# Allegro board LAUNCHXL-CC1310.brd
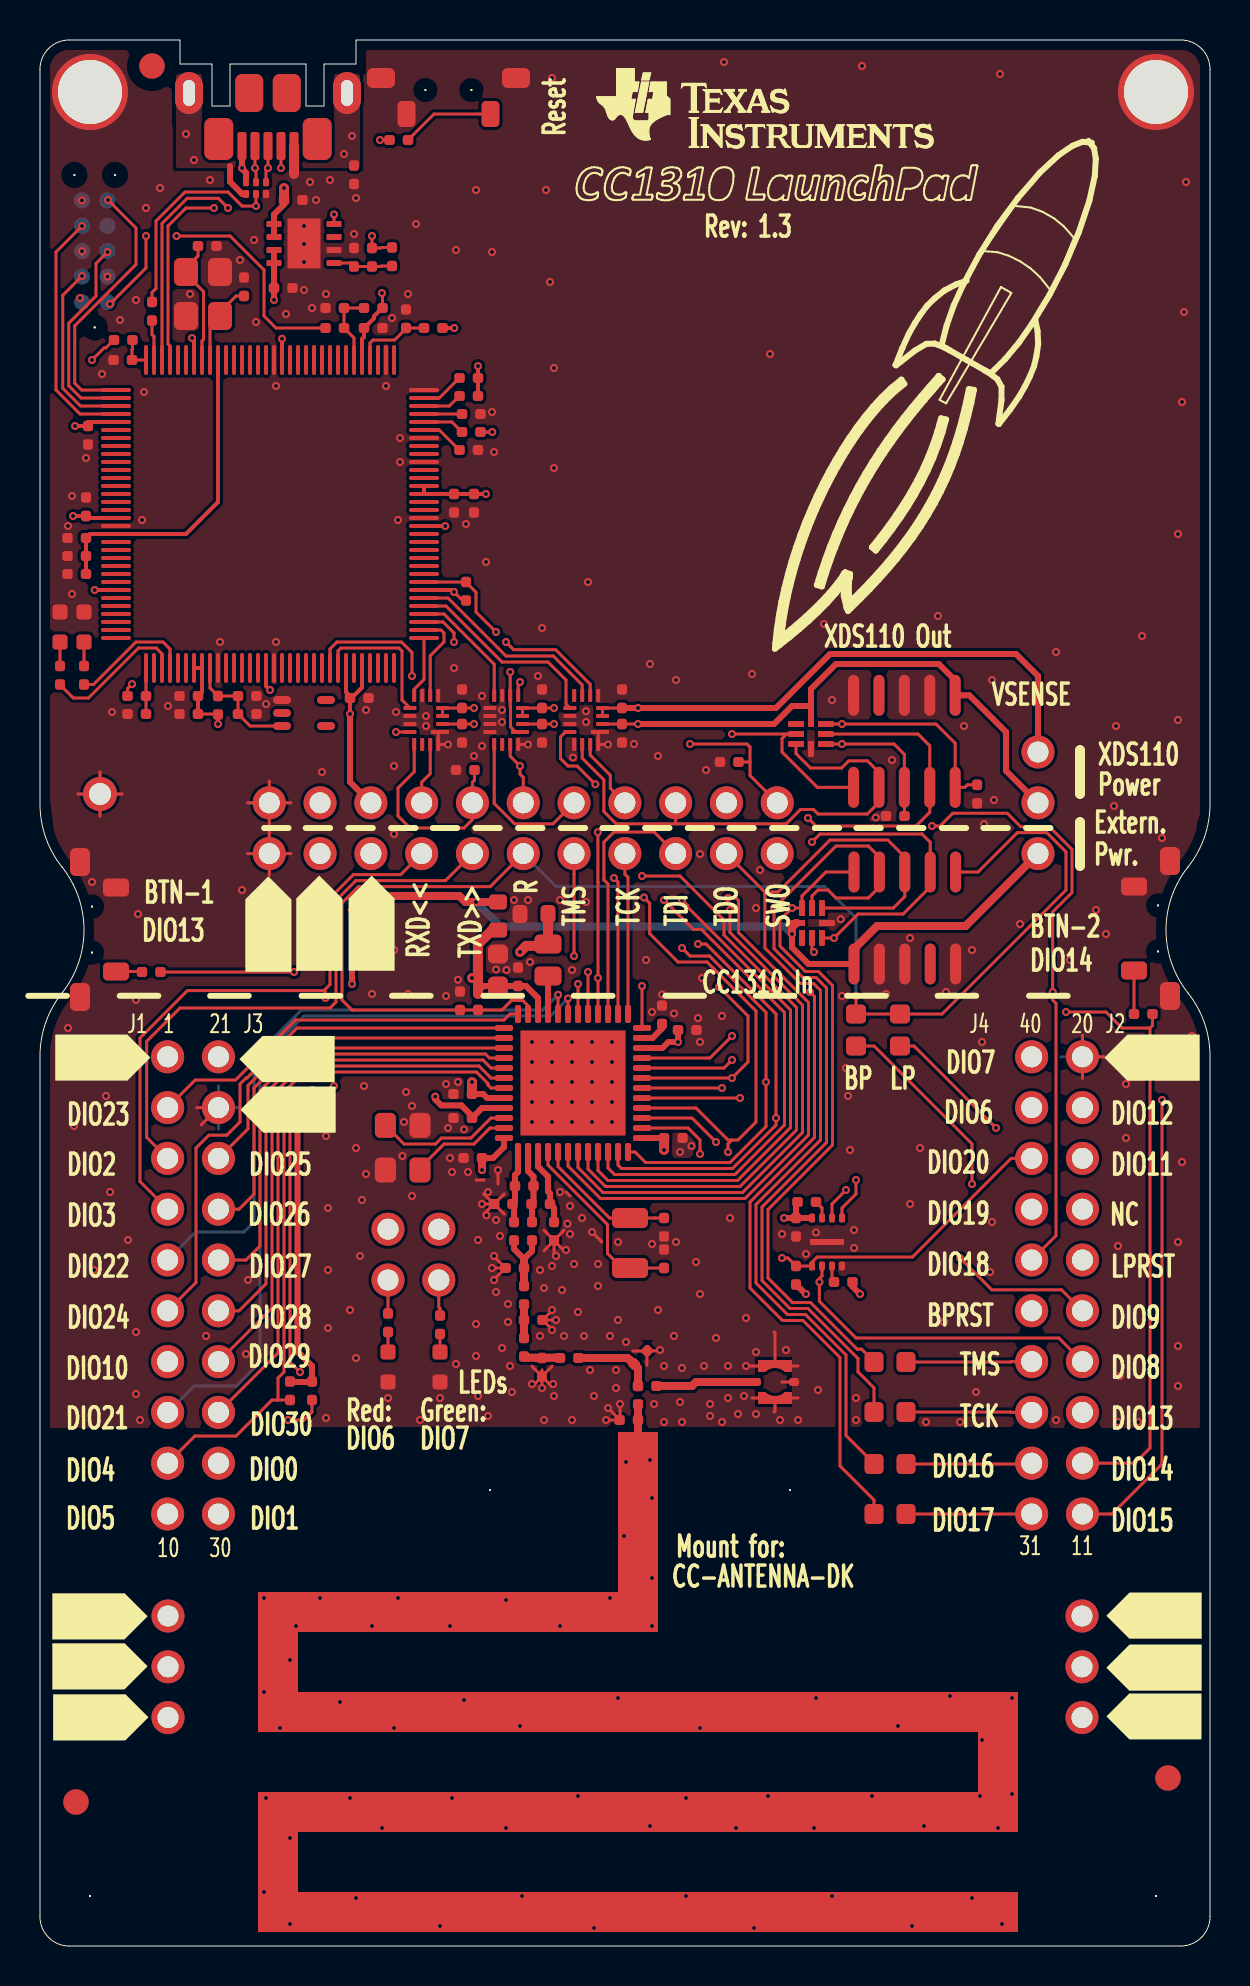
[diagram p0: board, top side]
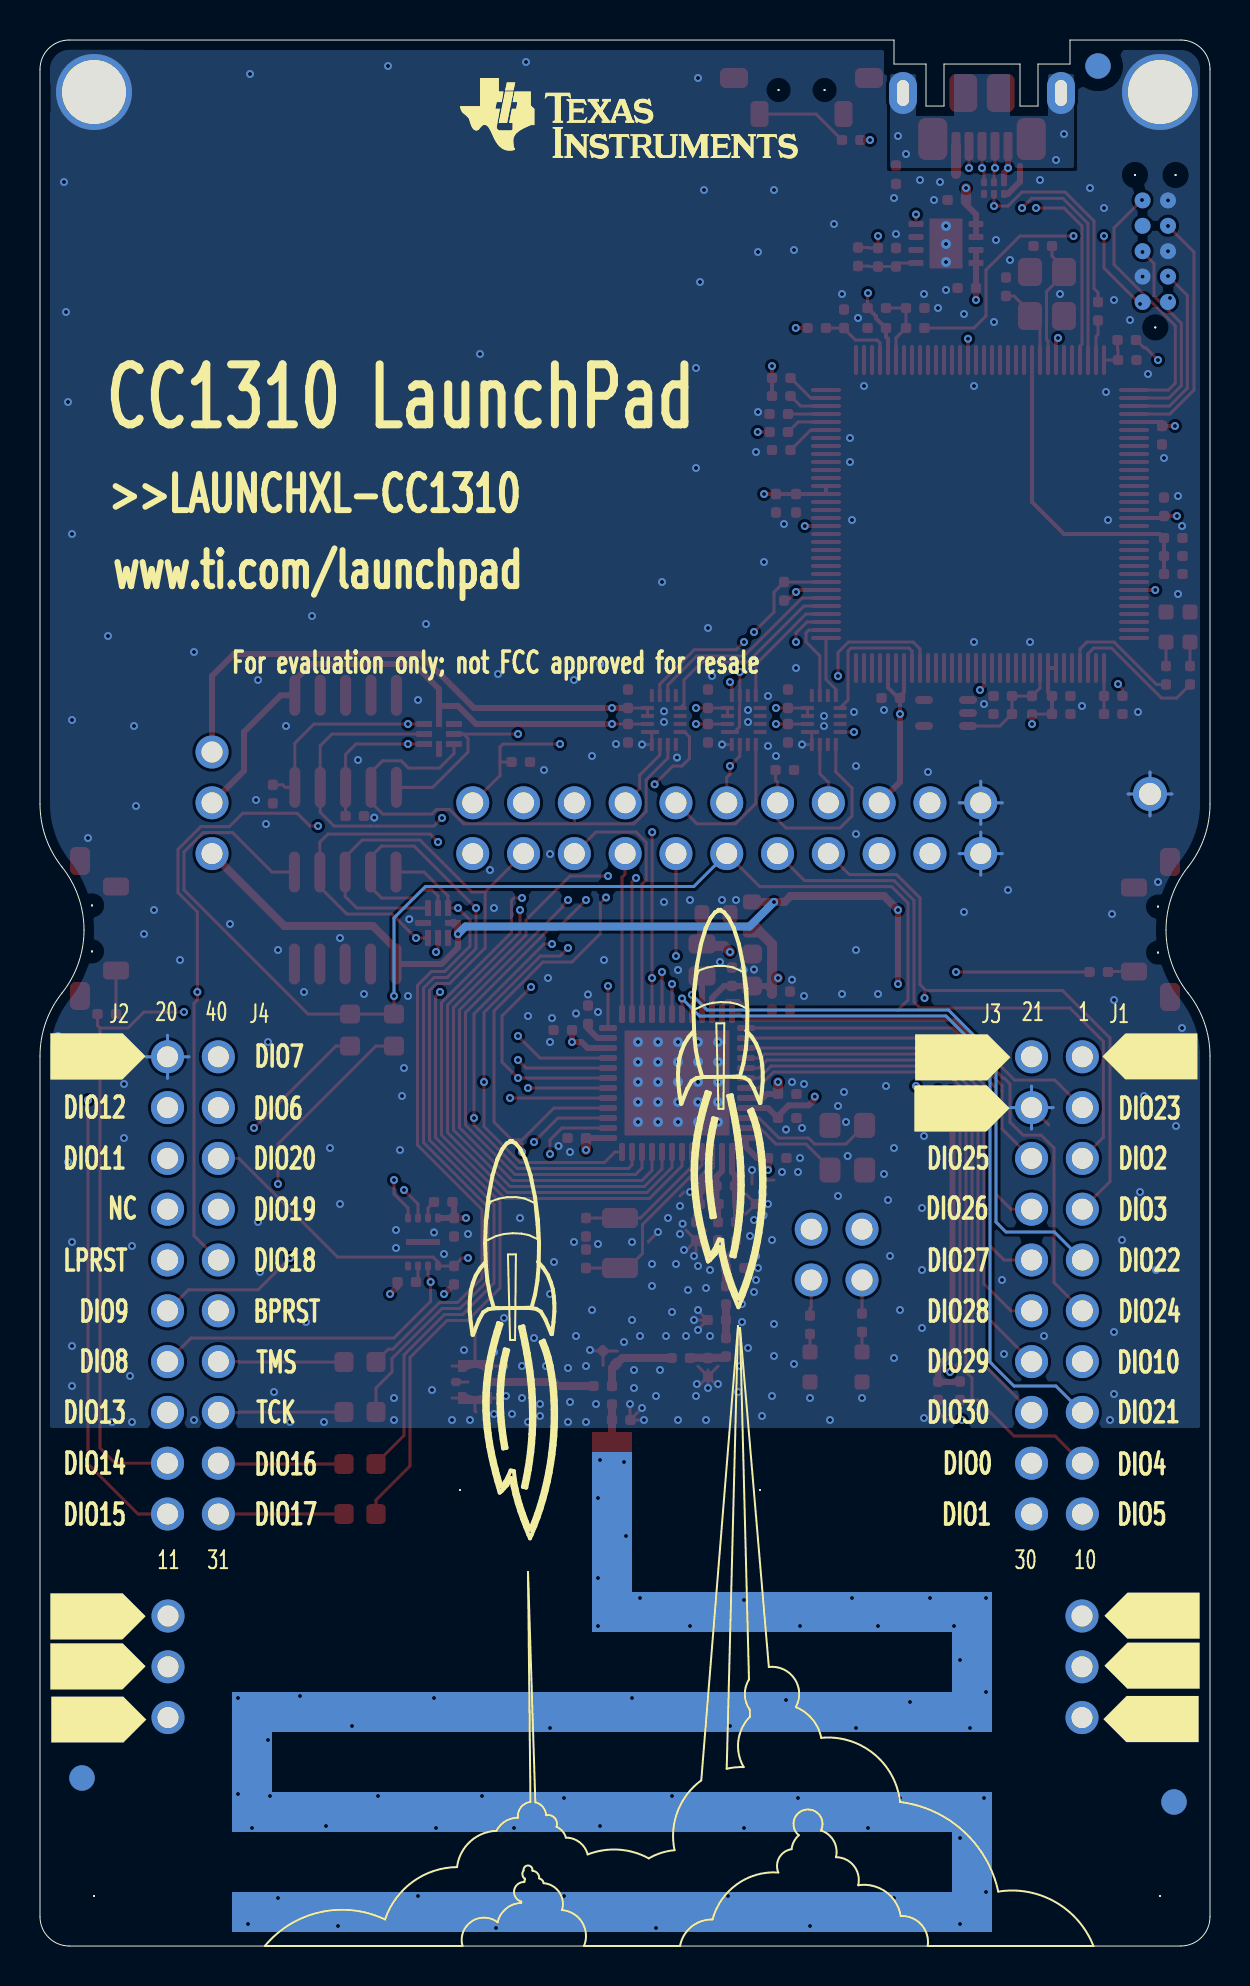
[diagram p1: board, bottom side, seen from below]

Outline 58.5 x 95.3 mm; copper layers: TOP, L2, L3, BOTTOM. Coordinates in mm from the lower left corner of the outline.
Outline path: 0,93.84 0,57.1 arc(0.28,55.43) 1.1,53.95 arc(1.92,52.47) 2.2,50.8 arc(1.92,49.13) 1.1,47.65 arc(0.28,46.17) 0,44.5 0,1.46 arc(0.43,0.43) 1.46,0 57.04,0 arc(58.07,0.43) 58.5,1.46 58.5,44.5 arc(58.22,46.17) 57.4,47.65 arc(56.58,49.13) 56.3,50.8 arc(56.58,52.47) 57.4,53.95 arc(58.22,55.43) 58.5,57.1 58.5,93.84 arc(58.07,94.87) 57.04,95.3 15.8,95.3 15.8,94.1 14.2,94.1 14.2,92 13.3,92 13.3,94.1 9.5,94.1 9.5,92 8.6,92 8.6,94.1 7,94.1 7,95.3 1.46,95.3 arc(0.43,94.87) 0,93.84

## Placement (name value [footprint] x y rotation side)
A1  868MHz/2440MHz  [ANTENNA_DN024N]  29.9 25.2 180 top
C3  100nF  [CAPC1005X60B2N]  31.2 40.4 0 top
C4  100nF  [CAPC1005X60B2N]  31.9 45.8 0 top
C5  100nF  [CAPC1005X60B2N]  21.6 42.6 180 top
C6  22uF  [CAPC1608X100A2N]  22.9 48 90 top
C7  100nF  [CAPC1005X60B2N]  23.9 48 90 top
C8  22uF  [CAPC1608X100A2L]  25.4 51.6 180 top
C9  100nF  [CAPC1005X60B2N]  22.1 39.4 180 top
C11  3.6pF  [CAPC1005X60B2N]  22.7 37.1 0 top
C12  2.7pF  [CAPC1005X60B2N]  24.2 33.9 180 top
C13  6.2pF  [CAPC1005X60B2N]  24.2 31.3 0 top
C14  3pF  [CAPC1005X60B2N]  25.1 29.4 270 top
C15  100pF  [CAPC1005X60B2N]  26 29.4 0 top
C16  100nF  [CAPC1005X60B2N]  21.6 41.4 180 top
C17  12pF  [CAPC1005X60B2N]  31.2 33.9 90 top
C18  12pF  [CAPC1005X60B2N]  31.2 36.4 270 top
C19  1uF  [CAPC1005X60B2N]  31.1 46.1 90 top
C20  100nF  [CAPC1005X60B2N]  21 46.8 90 top
C21  100pF  [CAPC1005X60B2N]  25.7 36.2 270 top
C22  3.6pF  [CAPC1005X60B2N]  24.6 36.2 270 top
C24  DNM  [CAPC1005X60B2N]  29.7 29.1 45 top
C30  100nF  [CAPC1005X60B2N]  37.8 36.4 270 top
C32  100nF  [CAPC1005X60B2N]  9.9 62.5 0 top
C33  12pF  [CAPC1005X60B2N]  10.2 82.5 90 top
C34  12pF  [CAPC1005X60B2N]  7.9 85 0 top
C35  10nF  [CAPC1005X60B2N]  15.5 62.4 0 top
C36  10nF  [CAPC1005X60B2N]  2.3 71.5 90 top
C37  10nF  [CAPC1005X60B2N]  2.4 76 270 top
C38  100nF  [CAPC1005X60B2N]  16.2 80.9 0 top
C39  100nF  [CAPC1005X60B2N]  20.7 72.6 270 top
C40  1uF  [CAPC1005X60B2N]  21.7 72.6 270 top
C41  10nF  [CAPC1005X60B2N]  7.9 62.5 180 top
C42  1uF  [CAPC1005X60B2N]  7.9 61.6 180 top
C43  100nF  [CAPC1005X60B2N]  2.3 70.4 180 top
C44  1uF  [CAPC1005X60B2N]  2.3 69.5 180 top
C45  2.2uF  [CAPC1005X60B2N]  2.3 68.6 180 top
C46  100nF  [CAPC1005X60B2N]  18.3 80.9 90 top
C47  15pF  [CAPC1005X60B2N]  16.6 84.9 270 top
C48  2.2uF  [CAPC1005X60B2N]  12.2 87.3 0 top
C49  2.2uF  [CAPC1005X60B2N]  11.7 82.9 0 top
C50  10nF  [CAPC1005X60B2N]  9.9 61.6 0 top
C52  100nF  [CAPC1005X60B2N]  21.1 61.9 90 top
C53  100nF  [CAPC1005X60B2N]  21.1 61.1 270 top
C54  100nF  [CAPC1005X60B2N]  25.1 61.9 90 top
C55  100nF  [CAPC1005X60B2N]  25.1 61.1 270 top
C56  100nF  [CAPC1005X60B2N]  29.1 61.9 90 top
C57  100nF  [CAPC1005X60B2N]  29.1 61.1 270 top
C58  DNM_0402  [CAPC1005X60B2N]  29.9 26.3 180 top
C59  100nF  [CAPC1005X60B2N]  4.6 79.3 180 top
CR1  LPL296-J2L2-25  [LEDC1707X65L]  20 28.2 90 top
CR2  LS L296-P2Q2-1  [LEDC1708X67L]  17.4 28.2 90 top
CR4  LS L296-P2Q2-1  [LEDC1708X67L]  1 66.7 270 top
CR5  LPL296-J2L2-25  [LEDC1707X65L]  2.2 66.7 270 top
CR6  TPD4E004DRY  [SON50P100X145X60-6N]  10.3 87.6 0 top
CR7  TPD6E004RSER  [QFN50P150X150X60-8N]  37.8 61.1 270 top
CR8  TPD6E004RSER  [QFN50P150X150X60-8N]  38.1 50.4 0 top
FIDU1  FIDU_1.27mm  [FID127X142]  5.6 94 0 top
FIDU2  FIDU_1.27mm  [FID127X142]  1.8 7.2 0 top
FIDU3  FIDU_1.27mm  [FID127X142]  56.4 8.4 0 top
FIDU4  FIDU_1.27mm  [FID127X142]  5.6 94 180 bottom
FIDU5  FIDU_1.27mm  [FID127X142]  1.8 7.2 180 bottom
FIDU6  FIDU_1.27mm  [FID127X142]  56.4 8.4 180 bottom
FL1  BLM18HE152SN1  [FIL_BLM18HE152SN1DL]  22.9 50.8 90 top
J1  SSQ-110-23-L-D  [SAMTEC_SSQ11023LD_A2B]  6.38 44.46 0 bottom
J2  SSQ-110-23-L-D  [SAMTEC_SSQ11023LD_A2B]  49.58 44.46 0 bottom
J6  105164-0001  [MOLEX_1051640001_A2N]  10.1 90 0 top
L1  6.8uH  [INDC2012X150L]  25.4 48.5 90 top
L12  7.5nH  [INDC1005X60B2N]  23.7 36.2 270 top
L13  6.8nH  [INDC1005X60B2N]  24.2 33 270 top
L14  6.8nH  [INDC1005X60B2N]  24.2 30.4 270 top
L22  27nH  [INDC1005X60B2N]  23.75 38 0 top
L23  7.5nH  [INDC1005X60B2N]  25.5 37.1 180 top
MH1  HOLE_3.2mm_NPL  [MTG320]  2.5 2.5 0 top
MH2  HOLE_3.2mm_NPL  [MTG320]  55.8 2.5 0 top
MH3  HOLE_3.2mm_PTH  [MTG320_380]  2.5 92.7 0 top
MH4  HOLE_3.2mm_PTH  [MTG320_380]  55.8 92.7 0 top
MH5  HOLE_1.1mm_PTH  [MTG110_170]  3 57.6 0 top
NOREF  -  []  0 79.15 0 top
NOREF#2  -  []  8.3 41.8 0 top
NOREF#3  -  []  51.5 42 0 top
NOREF#4  -  []  51.6 11.5 0 top
NOREF#5  #VALUE  [unnamed#2]  22.5 22.8 0 top
NOREF#6  -  []  17.8 48.7 90 top
NOREF#7  -  []  16.5 46.3 90 top
NOREF#8  -  []  -1.7 11.6 0 top
NOREF#9  -  []  13.8 46.4 90 top
NOREF#10  -  []  40.01 0 90 top
NOREF#11  -  []  -1.7 14.1 0 top
NOREF#12  -  []  51.6 14.1 0 top
NOREF#13  -  []  -1.8 8.9 0 top
NOREF#14  -  []  53.1 10.1 0 top
NOREF#15  -  []  0.7 43.2 0 top
NOREF#16  -  []  8.3 39.4 0 top
NOREF#17  -  []  58 10.1 180 bottom
NOREF#18  -  []  7 8.8 180 bottom
NOREF#19  -  []  60.3 14.1 180 bottom
NOREF#20  -  []  60.3 11.6 180 bottom
NOREF#21  -  []  17.1 39.5 180 bottom
NOREF#22  -  []  17.2 41.9 180 bottom
NOREF#23  -  []  5.6 43.1 180 bottom
NOREF#24  -  []  60.3 42.1 180 bottom
NOREF#25  -  []  7 11.6 180 bottom
NOREF#26  -  []  51.53 65.52 180 bottom
NOREF#27  -  []  7 14.1 180 bottom
P1  BB02-HC031-KB1-603000  [GRADCONN_BB02HC031KB1603000_A2B]  52.1 11.42 90 top
P2  BB02-HC031-KB1-603000  [GRADCONN_BB02HC031KB1603000_A2B]  6.4 11.42 90 top
P4  BB02-HJ221-KB1-603000  [GRADCONN_BB02HJ221KB160300_A2B]  36.86 57.16 180 top
P5  FTSH-105-01-F-DV-K  [SAMTEC_FTSH-105-01-F-DV-K-10L]  40.7 49.1 0 top
P6  BB02-HJ041-KB1-603000  [GRADCONN_BB02HJ041KB1603000_A2B]  17.4 33.3 0 top
P7  FTSH-105-01-F-DV-K  [SAMTEC_FTSH-105-01-F-DV-K-10L]  45.76 62.53 180 top
P8  TC2050-IDC-NL  [TAGCONNECT_TC2050IDCNLN]  2.1 82.2 90 bottom
P10  BB02-HC031-KB1-603000  [GRADCONN_BB02HC031KB1603000_A2B]  49.9 59.7 270 top
P11  MM5829-2700  [MURATA_MM58292700RJ4_A2N]  35.8 28.2 0 top
R1  100k  [RESC1005X40B2N]  21.9 46.8 90 top
R2  3.3k  [RESC1005X40B2N]  12.5 27.3 90 top
R3  3.3k  [RESC1005X40B2N]  13.6 27.3 90 top
R11  2.2k  [RESC1005X40B2N]  37.8 34 270 top
R12  1.8pF  [CAPC1005X60B2N]  29.9 28 270 top
R13  0  [RESC1005X40B2N]  29.9 28 0 top
R14  220  [RESC1005X40B2N]  17.4 30.7 90 top
R15  180  [RESC1005X40B2N]  20 30.6 90 top
R17  10k  [RESC1005X40B2N]  16.2 81.9 0 top
R18  4.7k  [RESC1005X40B2N]  8.9 62.5 270 top
R19  DNM  [RESC1005X40B2N]  5.6 82.2 270 top
R20  100  [RESC1005X40B2N]  15.2 80.9 180 top
R21  DNM  [RESC1005X40B2N]  15.2 81.9 180 top
R22  330k  [RESC1005X40B2N]  5.3 62.5 180 top
R23  180  [RESC1005X40B2N]  1 64 270 top
R24  220k  [RESC1005X40B2N]  5.3 61.6 180 top
R25  220  [RESC1005X40B2N]  2.2 64 270 top
R27  1k  [RESC1005X40B2N]  21.9 77.5 180 top
R28  4.87k  [RESC1005X40B2N]  21.9 74.8 180 top
R29  1k  [RESC1005X40B2N]  21.1 76.6 0 top
R30  1k  [RESC1005X40B2N]  21.1 75.7 0 top
R31  51  [RESC1005X40B2N]  19.2 80.9 0 top
R32  33k  [RESC1005X40B2N]  15.7 88.1 90 top
R33  51k  [RESC1005X40B2N]  17.6 84 90 top
R34  30k  [RESC1005X40B2N]  15.7 84.9 270 top
R39  1k  [RESC1005X40B2N]  21.9 78.4 180 top
R46  DNM  [RESC1608X55N]  43.3 29.2 180 top
R47  DNM  [RESC1608X55N]  43.3 26.7 180 top
R48  DNM  [RESC1608X55N]  43.3 24.1 180 top
R49  DNM  [RESC1608X55N]  43.3 21.6 180 top
R51  DNM  [RESC1608X55N]  40.8 45 90 top
R52  0  [RESC1608X55N]  43 46.6 270 top
R55  100  [RESC1005X40B2N]  54.7 46.6 0 top
R56  100  [RESC1005X40B2N]  5.1 48.7 0 top
R57  100  [RESC1005X40B2N]  18.4 90.3 180 top
R58  3.3k  [RESC1005X40B2N]  21.3 68.2 270 top
R59  DNM  [RESC1005X40B2N]  39.7 33.2 0 top
R60  DNM  [RESC1005X40B2N]  38.8 37.2 180 top
R61  100k  [RESC1005X40B2N]  20.8 58.8 0 top
R62  100k  [RESC1005X40B2N]  34 59.2 0 top
R63  100k  [RESC1005X40B2N]  42.3 56.5 0 top
R65  100k  [RESC1005X40B2N]  46.86 57.14 90 top
R66  100  [RESC1005X40B2N]  3.7 80.3 0 top
SW1  1188E-1K2-V  [SW_1188E1K2V_A2N]  2 54.2 270 top
SW2  1188E-1K2-V  [SW_1188E1K2V_A2N]  56.5 47.5 90 top
SW3  1188E-1K2-V  [SW_1188E1K2V_A2N]  23.8 93.4 180 top
U1  CC1310F128RGZT  [QFNFC50P700X700X100-49A2N]  23.9 39.7 0 top
U4  MX25R8035FZUIL0  [SON50P300X200X60-9B2L]  38.6 34 0 top
U5  TM4C1294NCPDTT3R  [QFP40P1600X1600X120-128N]  5.3 63.9 0 top
U6  LM4040B25IDCK  [SOT65P210X110-5N]  12.1 62.3 270 top
U7  TPS79601DR  [SON65P300X300X100-9AL]  11.7 86.1 270 top
U8  SN74AVC4T245RSV  [QFNFC40P180X260X55-16A2L]  20 60.7 90 top
U9  SN74AVC4T245RSV  [QFNFC40P180X260X55-16A2L]  28 60.7 90 top
U10  SN74AVC4T245RSV  [QFNFC40P180X260X55-16A2L]  24 60.7 90 top
UNK#REFDES  -  []  28.8 93.9 0 top
UNK#REFDES#2  -  []  36.5 93.4 180 bottom
Y1  32.768kHz  [XTAL_FC-135N]  29.5 33.9 90 top
Y2  24MHz  [OSCCC250X320X60-4L]  19 38.8 90 top
Y3  16MHz  [OSCCC250X320X100-4BN]  9 81.5 90 top

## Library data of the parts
A1 = ANTENNA_PCB: User Part Number: #PN
C3-C5 C7 C9 C11-C22 C24 C30 C32-C50 C52-C59 = CAPACITOR: User Part Number: #PN
C6 C8 = CAPACITOR: User Part Number: #PN; alternate symbols: (CAPC1608X100A2L,CAPC1608X100A2M)
CR1 CR5 = LED: alternate symbols: (LEDC1707X65L,LEDC1707X65M)
CR2 CR4 = LED: alternate symbols: (LEDC1708X67L,LEDC1708X67M)
CR6 = DIODE_TPD4E004_SON6: User Part Number: #PN; alternate symbols: (SON50P100X145X65-6L,SON50P100X145X65-6M)
CR7 CR8 = DIODE_TVS_TPD6E004_QFN8_V1_0: alternate symbols: (QFN50P150X150X60-8L,QFN50P150X150X60-8M,QFN50P150X150X60-8AL)
FIDU1-FIDU6 = FIDMARK
FL1 = FILTER_2PIN: alternate symbols: (FIL_BLM18HE152SN1DL,FIL_BLM18HE152SN1DM)
J1 J2 = CONN_HEADER_2X10_J_S_V1: User Part Number: #PN; alternate symbols: (SAMTEC_SSQ11023LD_A2C,SAMTEC_SSQ11023LD_A2A)
J6 = CONN_USB_MICRO_B_2MH: User Part Number: #PN; alternate symbols: (MOLEX_1051640001_A2L,MOLEX_1051640001_A2M)
L1 = INDUCTOR: alternate symbols: (INDC2012X150L,INDC2012X150M)
L12-L14 L22 L23 = INDUCTOR: User Part Number: #PN
MH1 MH2 = HOLE_NPL
MH3-MH5 = HOLE_PTH
NOREF#5 = -: User Part Number: #PN
P1 P2 P10 = CONN_HEADER_3_P_S: User Part Number: #PN; alternate symbols: (GRADCONN_BB02HC031KB1603000_A2C,GRADCONN_BB02HC031KB1603000_A2A)
P4 = CONN_HEADER_2X11_P_S: User Part Number: #PN; alternate symbols: (GRADCONN_BB02HJ221KB160300_A2C,GRADCONN_BB02HJ221KB160300_A2A)
P5 P7 = CONN_HEADER_2X5: alternate symbols: (SAMTEC_FTSH-105-01-F-DV-K-10L,SAMTEC_FTSH-105-01-F-DV-K-10M)
P6 = CONN_HEADER_2X2_P: User Part Number: #PN; alternate symbols: (GRADCONN_BB02HJ041KB1603000_A2C,GRADCONN_BB02HJ041KB1603000_A2A)
P8 = CONN_IDC_TC2050-IDC-NL: User Part Number: #PN; alternate symbols: (TAGCONNECT_TC2050IDCNLL,TAGCONNECT_TC2050IDCNLM)
P11 = CONN_COAX_1_1_P_2MH: User Part Number: #PN; alternate symbols: (MURATA_MM58292700RJ4_A2L,MURATA_MM58292700RJ4_A2M)
R1-R3 R11 R13-R15 R17-R25 R27-R34 R39 R55-R63 R65 R66 = RESISTOR: User Part Number: #PN
R12 = CAPACITOR: User Part Number: #PN; alternate symbols: (CAPC1005X60B2L,CAPC1005X60B2M)
R46-R49 R51 R52 = RESISTOR: alternate symbols: (RESC1608X55L,RESC1608X55M)
SW1-SW3 = SWITCH_TACT_V2: alternate symbols: (SW_1188E1K2V_A2L,SW_1188E1K2V_A2M)
U1 = IC_RF_CC1310F128RGZT_VQFN48: User Part Number: #PN; alternate symbols: (QFNFC50P700X700X100-49A2L,QFNFC50P700X700X100-49A2M)
U4 = IC_FLASH_MX25R8035F_USON8: User Part Number: #PN; alternate symbols: (SON50P300X200X60-9B2L,SON50P300X200X60-9B2M)
U5 = IC_PROC_TM4C1294NCPDT_TQFP128: alternate symbols: (QFP40P1600X1600X120-128L,QFP40P1600X1600X120-128M)
U6 = IC_REF_LM4040_SC70-5: alternate symbols: (SOT65P210X110-5L,SOT65P210X110-5M)
U7 = IC_PM_TPS79601_SON8: alternate symbols: (SON65P300X300X100-9AL,SON65P300X300X100-9AM)
U8-U10 = IC_XCVR_SN74AVC4T245_UQFN16_2: User Part Number: #PN; alternate symbols: (QFNFC40P180X260X55-16A2L,QFNFC40P180X260X55-16A2M)
Y1 = CRYSTAL: alternate symbols: (XTAL_FC-135L,XTAL_FC-135M)
Y2 = XTAL_4PIN_S: alternate symbols: (OSCCC250X320X60-4L,OSCCC250X320X60-4M)
Y3 = XTAL_4: alternate symbols: (OSCCC250X320X100-4BL,OSCCC250X320X100-4BM)

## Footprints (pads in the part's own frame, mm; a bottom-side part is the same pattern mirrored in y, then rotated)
ANTENNA_DN024N
  rect 2x1 smd: 1(0,0)
CAPC1005X60B2N
  custom 0.125x0.125 smd: 1(0,0) 2(0.924,0)
CAPC1608X100A2L
  custom 0.188x0.188 smd: 1(0,0) 2(1.4,0)
CAPC1608X100A2N
  custom 0.237x0.237 smd: 1(0,0) 2(1.6,0)
FID127X142
  round 1.27 smd: 1(0,0)
FIL_BLM18HE152SN1DL
  custom 0.188x0.188 smd: 1(0,0) 2(1.4,0)
GRADCONN_BB02HC031KB1603000_A2B
  round 1.65 hole 1.05: 1(0,0) 2(2.54,0) 3(5.08,0)
GRADCONN_BB02HJ041KB1603000_A2B
  round 1.65 hole 1.05: 1(0,0) 2(0,2.54) 3(2.54,0) 4(2.54,2.54)
GRADCONN_BB02HJ221KB160300_A2B
  round 1.65 hole 1.05: 1(0,0) 2(0,2.54) 3(2.54,0) 4(2.54,2.54) 5(5.08,0) 6(5.08,2.54) 7(7.62,0) 8(7.62,2.54) 9(10.16,0) 10(10.16,2.54) 11(12.7,0) 12(12.7,2.54) 13(15.24,0) 14(15.24,2.54) 15(17.78,0) 16(17.78,2.54) 17(20.32,0) 18(20.32,2.54) 19(22.86,0) 20(22.86,2.54) 21(25.4,0) 22(25.4,2.54)
INDC1005X60B2N
  custom 0.125x0.125 smd: 1(0,0) 2(0.924,0)
INDC2012X150L
  custom 0.237x0.237 smd: 1(0,0) 2(1.6,0)
LEDC1707X65L
  custom 0.188x0.188 smd: 1(0,0) 2(1.501,0)
LEDC1708X67L
  custom 0.188x0.188 smd: 1(0,0) 2(1.501,0)
MOLEX_1051640001_A2N
  custom 0.362x0.362 smd: (-1.162,0.35) (3.762,0.35)
  custom 0.35x0.35 smd: (0.362,2.65) (2.238,2.65)
  custom 0.113x0.113 smd: 1(0,0) 2(0.65,0) 3(1.3,0) 4(1.95,0) 5(2.6,0)
  oval 1.4x2.1 hole 0.6x1.3: M1(-2.65,2.65) M2(5.25,2.65)
MTG110_170
  round 1.699 hole 1.1: 1(0,0)
MTG320
  round 0.099 hole 3.2 unplated: (0,0)
MTG320_380
  round 3.8 hole 3.2: 1(0,0)
MURATA_MM58292700RJ4_A2N
  custom 0.1x0.1 smd: 1(0,0) 2(1.9,0)
  custom 0.15x0.15 smd: M1(0.95,-0.8) M2(0.95,0.8)
OSCCC250X320X60-4L
  custom 0.263x0.263 smd: 1(0,0) 2(2.23,0) 3(2.23,1.73) 4(0,1.73)
OSCCC250X320X100-4BN
  custom 0.299x0.299 smd: 1(0,0) 2(2.2,0) 3(2.2,1.699) 4(0,1.699)
QFN50P150X150X60-8N
  custom 0.075x0.075 smd: 1(0,0) 2(0.5,0) 3(1,0) 4(1.25,0.75) 5(1,1.5) 6(0.5,1.5) 7(0,1.5) 8(-0.25,0.75)
QFNFC40P180X260X55-16A2L
  custom 0.05x0.05 smd: 1(0,0) 2(0.4,-0.125) 3(0.8,-0.125) 4(1.2,-0.125) 5(1.825,0.09) 6(1.825,0.49) 7(1.825,0.89) 8(1.825,1.29) 9(1.2,1.505) 10(0.8,1.505) 11(0.4,1.505) 12(0,1.505) 13(-0.625,1.29) 14(-0.625,0.89) 15(-0.625,0.49) 16(-0.625,0.09)
QFNFC50P700X700X100-49A2N
  custom 0.075x0.075 smd: 1(0,0) 2(0.5,0) 3(1,0) 4(1.5,0) 5(2,0) 6(2.5,0) 7(3,0) 8(3.5,0) 9(4,0) 10(4.5,0) 11(5,0) 12(5.5,0) 13(6.2,0.7) 14(6.2,1.2) 15(6.2,1.7) 16(6.2,2.2) 17(6.2,2.7) 18(6.2,3.2) 19(6.2,3.7) 20(6.2,4.2) 21(6.2,4.7) 22(6.2,5.2) 23(6.2,5.7) 24(6.2,6.2) 25(5.5,6.9) 26(5,6.9) 27(4.5,6.9) 28(4,6.9) 29(3.5,6.9) 30(3,6.9) 31(2.5,6.9) 32(2,6.9) 33(1.5,6.9) 34(1,6.9) 35(0.5,6.9) 36(0,6.9) 37(-0.7,6.2) 38(-0.7,5.7) 39(-0.7,5.2) 40(-0.7,4.7) 41(-0.7,4.2) 42(-0.7,3.7) 43(-0.7,3.2) 44(-0.7,2.7) 45(-0.7,2.2) 46(-0.7,1.7) 47(-0.7,1.2) 48(-0.7,0.7)
  rect 5.25x5.25 smd: 49(2.75,3.45)
QFP40P1600X1600X120-128N
  oval 0.201x1.501 smd: 1(0,0) 2(0.399,0) 3(0.8,0) 4(1.199,0) 5(1.6,0) 6(1.999,0) 7(2.4,0) 8(2.799,0) 9(3.2,0) 10(3.599,0) 11(4,0) 12(4.399,0) 13(4.801,0) 14(5.199,0) 15(5.601,0) 16(6,0) 17(6.401,0) 18(6.8,0) 19(7.201,0) 20(7.6,0) 21(8.001,0) 22(8.4,0) 23(8.801,0) 24(9.2,0) 25(9.601,0) 26(10,0) 27(10.399,0) 28(10.8,0) 29(11.199,0) 30(11.6,0) 31(11.999,0) 32(12.4,0) 65(12.4,15.4) 66(11.999,15.4) 67(11.6,15.4) 68(11.199,15.4) 69(10.8,15.4) 70(10.399,15.4) 71(10,15.4) 72(9.601,15.4) 73(9.2,15.4) 74(8.801,15.4) 75(8.4,15.4) 76(8.001,15.4) 77(7.6,15.4) 78(7.201,15.4) 79(6.8,15.4) 80(6.401,15.4) 81(6,15.4) 82(5.601,15.4) 83(5.199,15.4) 84(4.801,15.4) 85(4.399,15.4) 86(4,15.4) 87(3.599,15.4) 88(3.2,15.4) 89(2.799,15.4) 90(2.4,15.4) 91(1.999,15.4) 92(1.6,15.4) 93(1.199,15.4) 94(0.8,15.4) 95(0.399,15.4) 96(0,15.4)
  oval 1.501x0.201 smd: 33(13.899,1.501) 34(13.899,1.9) 35(13.899,2.301) 36(13.899,2.7) 37(13.899,3.099) 38(13.899,3.5) 39(13.899,3.899) 40(13.899,4.3) 41(13.899,4.699) 42(13.899,5.1) 43(13.899,5.499) 44(13.899,5.9) 45(13.899,6.299) 46(13.899,6.7) 47(13.899,7.099) 48(13.899,7.501) 49(13.899,7.899) 50(13.899,8.301) 51(13.899,8.7) 52(13.899,9.101) 53(13.899,9.5) 54(13.899,9.901) 55(13.899,10.3) 56(13.899,10.701) 57(13.899,11.1) 58(13.899,11.501) 59(13.899,11.9) 60(13.899,12.301) 61(13.899,12.7) 62(13.899,13.099) 63(13.899,13.5) 64(13.899,13.899) 97(-1.501,13.899) 98(-1.501,13.5) 99(-1.501,13.099) 100(-1.501,12.7) 101(-1.501,12.301) 102(-1.501,11.9) 103(-1.501,11.501) 104(-1.501,11.1) 105(-1.501,10.701) 106(-1.501,10.3) 107(-1.501,9.901) 108(-1.501,9.5) 109(-1.501,9.101) 110(-1.501,8.7) 111(-1.501,8.301) 112(-1.501,7.899) 113(-1.501,7.501) 114(-1.501,7.099) 115(-1.501,6.7) 116(-1.501,6.299) 117(-1.501,5.9) 118(-1.501,5.499) 119(-1.501,5.1) 120(-1.501,4.699) 121(-1.501,4.3) 122(-1.501,3.899) 123(-1.501,3.5) 124(-1.501,3.099) 125(-1.501,2.7) 126(-1.501,2.301) 127(-1.501,1.9) 128(-1.501,1.501)
RESC1005X40B2N
  custom 0.125x0.125 smd: 1(0,0) 2(0.924,0)
RESC1608X55N
  custom 0.237x0.237 smd: 1(0,0) 2(1.6,0)
SAMTEC_FTSH-105-01-F-DV-K-10L
  oval 0.551x2.05 smd: 1(0,0) 2(0,4.6) 3(1.27,0) 4(1.27,4.6) 5(2.54,0) 6(2.54,4.6) 7(3.81,0) 8(3.81,4.6) 9(5.08,0) 10(5.08,4.6)
SAMTEC_SSQ11023LD_A2B
  round 1.65 hole 1.05: 1(0,0) 2(2.54,0) 3(0,2.54) 4(2.54,2.54) 5(0,5.08) 6(2.54,5.08) 7(0,7.62) 8(2.54,7.62) 9(0,10.16) 10(2.54,10.16) 11(0,12.7) 12(2.54,12.7) 13(0,15.24) 14(2.54,15.24) 15(0,17.78) 16(2.54,17.78) 17(0,20.32) 18(2.54,20.32) 19(0,22.86) 20(2.54,22.86)
SON50P100X145X60-6N
  custom 0.075x0.075 smd: 1(0,0) 2(0.5,0) 3(1.001,0) 4(1.001,0.589) 5(0.5,0.589) 6(0,0.589)
SON50P300X200X60-9B2L
  custom 0.075x0.075 smd: 1(0,0) 2(0.5,0) 3(1,0) 4(1.5,0) 5(1.5,2.4) 6(1,2.4) 7(0.5,2.4) 8(0,2.4)
  rect 1.7x0.3 smd: 9(0.75,1.2)
SON65P300X300X100-9AL
  custom 0.075x0.075 smd: 1(0,0) 2(0.65,0) 3(1.3,0) 4(1.95,0) 5(1.95,3) 6(1.3,3) 7(0.65,3) 8(0,3)
  rect 2.5x1.65 smd: 9(0.975,1.5)
SOT65P210X110-5N
  oval 0.399x0.899 smd: 1(0,0) 2(0.65,0) 3(1.3,0) 4(1.3,2.2) 5(0,2.2)
SW_1188E1K2V_A2N
  round 0.099 hole 0.899 unplated: (2.229,0.6) (4.529,0.6)
  custom 0.25x0.25 smd: 1(0,0) 2(6.75,0)
  custom 0.225x0.225 smd: 3(1.275,1.8) 4(5.475,1.8)
TAGCONNECT_TC2050IDCNLN
  round 0.099 hole 1.001 unplated: (-1.27,0.635) (6.35,-0.38) (6.35,1.65)
  round 0.8 smd: 1(0,0) 2(1.27,0) 3(2.54,0) 4(3.81,0) 5(5.08,0) 6(5.08,1.27) 7(3.81,1.27) 8(2.54,1.27) 9(1.27,1.27) 10(0,1.27)
unnamed#2
  round 0.099 hole 3.2 unplated: (0,0) (15,0)
XTAL_FC-135N
  custom 0.25x0.25 smd: 1(0,0) 2(2.499,0)

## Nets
+5V: J1.2 P2.1 P4.20
GND: C3.2 C4.2 C5.2 C6.2 C7.2 C8.2 C9.2 C11.1 C12.2 C13.2 C14.2 C16.2 C17.2 C18.2 C19.2 C20.2 C21.2 C24.2 C30.2 C32.2 C33.2 C34.2 C35.2 C36.2 C37.2 C38.2 C39.2 C40.2 C41.2 C42.2 C43.2 C44.2 C45.2 C46.2 C48.2 C49.2 C50.2 C52.2 C53.2 C54.2 C55.2 C56.2 C57.2 C58.2 C59.2 CR1.1(C) CR2.1(C) CR4.1(C) CR5.1(C) CR6.3 CR7.4(GND) CR8.4(GND) J1.4 J2.2 J6.5(GND) MH3.1 MH4.1 MH5.1 P1.2 P1.3 P2.2 P2.3 P4.21 P4.22 P5.3 P5.5 P5.9 P7.3 P7.5 P7.9 P8.3(7) P8.5(8) P8.9(10) P11.2 P11.M1 P11.M2 R21.2 R24.2 R28.1 R29.2 R32.1 R34.1 R61.1 R62.1 R63.1 R65.1 SW1.1 SW1.2 SW1.3 SW2.1 SW2.2 SW2.4 SW3.1 SW3.2 SW3.4 U1.49(EGP/GND) U4.4(GND) U4.9(EGP) U5.10(GNDA) U5.17(GND#17) U5.48(GND#48) U5.55(GND#55) U5.58(GND#58) U5.64(NWAKE) U5.66(XOSC0) U5.80(GND#80) U5.114(GND#114) U6.1(ANODE) U7.6(GND) U7.9(GND/TAB) U8.1(1NOE) U8.5(2DIR) U8.7(1A2) U8.10(GND#10) U8.11(GND#11) U8.16(2NOE) U9.1(1NOE) U9.5(2DIR) U9.10(GND#10) U9.11(GND#11) U9.13(2B1) U9.16(2NOE) U10.7(1A2) U10.9(2A2) U10.10(GND#10) U10.11(GND#11) U10.12(2B2) U10.16(2NOE) Y2.2 Y2.4 Y3.2(GND) Y3.4(NC_4)
VDDC: C43.1 C44.1 C45.1 U5.87(VDDC#87) U5.115(VDDC#115)
VDDR: C8.1 C9.1 C16.1 L1.2 U1.45(VDDR) U1.48(VDDR_RF)
VDDS: C3.1 C4.1 C5.1 C6.1 C7.1 FL1.1 R1.2 U1.13(VDDS2) U1.22(VDDS3) U1.34(VDDS_DCDC) U1.44(VDDS)
BP_RESET: J2.11 R52.2
CC1310_RESET: C20.1 CR8.2(IO2) P4.12 P5.10 R1.1 R51.2 R52.1 U1.35(RESET_N)
CC1310_RXD: J1.7 P4.16 U1.7(DIO_2)
CC1310_SWO: J2.9 P4.2 U1.28(DIO_18)
CC1310_TCK: CR8.6(IO5) P4.8 P5.4 R47.2 U1.25(JTAG_TCKC)
CC1310_TMS: CR8.7(IO6) P4.10 P5.2 R46.2 U1.24(JTAG_TMSC)
CC1310_TXD: J1.5 P4.14 U1.8(DIO_3)
CC1310_VDD: C30.1 CR8.8(VCC) FL1.2 J1.1 P1.1 P4.18 P5.1 P10.3 R2.2 R3.2 R11.2 R59.2 R60.2 U4.8(VCC)
DCDC_SW: L1.1 U1.33(DCDC_SW)
DIO1: J1.20 U1.6(DIO_1)
DIO4_SCL: J1.17 R2.1 U1.9(DIO_4)
DIO5_SDA: J1.19 R3.1 U1.10(DIO_5)
DIO6_RLED: J2.3 P6.2 U1.11(DIO_6)
DIO7_GLED: J2.1 P6.4 U1.12(DIO_7)
DIO8_MISO: J2.14 U1.14(DIO_8) U4.2(SO/SIO1)
DIO9_MOSI: J2.12 U1.15(DIO_9) U4.5(SI/SIO0)
DIO10_SCLK: J1.13 U1.16(DIO_10) U4.6(SCLK)
DIO11_CS: J2.6 U1.17(DIO_11)
DIO12: J2.4 U1.18(DIO_12)
DIO13_BTN1: J2.16 R56.2 U1.19(DIO_13)
DIO14_BTN2: J2.18 R55.2 U1.20(DIO_14)
DIO15: J2.20 U1.21(DIO_15)
DIO16_TDO: CR8.5(IO4) P4.4 P5.6 R48.2 U1.26(DIO_16)
DIO17_TDI: CR8.3(IO3) P4.6 P5.8 R49.2 U1.27(DIO_17)
DIO19_CTS: J2.7 U1.29(DIO_19)
DIO20_FLASH_CS: J2.5 R11.1 U1.30(DIO_20) U4.1(NCS)
DIO21: J1.15 U1.31(DIO_21)
DIO22: J1.9 U1.32(DIO_22)
DIO23_ANALOG: J1.3 U1.36(DIO_23)
DIO24_ANALOG: J1.11 U1.37(DIO_24)
DIO25_ANALOG: J1.6 U1.38(DIO_25)
DIO26_ANALOG: J1.8 U1.39(DIO_26)
DIO27_ANALOG: J1.10 U1.40(DIO_27)
DIO28_ANALOG: J1.12 U1.41(DIO_28)
DIO29_ANALOG: J1.14 U1.42(DIO_29)
DIO30_ANALOG: J1.16 U1.43(DIO_30)
IRSTN: P8.10(5) R20.2
ITCK: P8.4(2) U5.100(PC0/TCK/SWCLK)
ITDI: P8.8(4) U5.98(PC2/TDI)
ITDO: P8.6(3) U5.97(PC3/TDO/SWO)
ITMS: P8.2(1) U5.99(PC1/TMS/SWDIO)
LP_RESET: J2.10 R51.1
USB_DM: CR6.5 J6.2(D-) U5.93(PL7/USB0DM)
USB_DP: CR6.4 J6.3(D+) U5.94(PL6/USB0DP)
USB_ID: CR6.2 J6.4(ID) R19.1
USB_VBUS: C48.1 CR6.6 J6.1(VCC) P4.19 R22.2 R66.1 U7.1(IN#1) U7.2(IN#2) U7.8(EN)
V-SENSE: C53.1 C55.1 C57.1 CR7.8(VCC) P7.1 P10.2 U8.2(VCCB) U9.2(VCCB) U10.2(VCCB)
XDS_RESET: R58.1 U5.40(PA6) U10.1(1NOE) U10.6(1A1)
XDS_RESET_LS: CR7.2(IO2) P4.11 P7.10 R57.2 U10.15(1B1)
XDS_RX: U5.33(PA0/U0RX) U8.8(2A1)
XDS_RX_LS: P4.13 R61.2 U8.13(2B1)
XDS_SWO: U5.25(PC4/C1-) U8.9(2A2)
XDS_SWO_LS: P4.1 R62.2 U8.12(2B2)
XDS_TCK: U5.35(PA2/SSI0CLK) U9.6(1A1)
XDS_TCK_LS: CR7.6(IO5) P4.7 P7.4 U9.15(1B1)
XDS_TDI: U5.38(PA5/SSI0XDAT1) U9.7(1A2)
XDS_TDI_LS: CR7.3(IO3) P4.5 P7.8 U9.14(1B2)
XDS_TDO: U5.37(PA4/SSI0XDAT0) U9.9(2A2)
XDS_TDO_LS: CR7.5(IO4) P4.3 P7.6 R63.2 U9.12(2B2)
XDS_TMS: U5.36(PA3/SSI0FSS) U10.8(2A1)
XDS_TMS_DIR: U5.24(PC5/C1+) U10.5(2DIR)
XDS_TMS_LS: CR7.7(IO6) P4.9 P7.2 R65.2 U10.13(2B1)
XDS_TX: U5.34(PA1/U0TX) U8.6(1A1)
XDS_TX_LS: P4.15 U8.15(1B1)
XDS_VCC: C35.1 C36.1 C37.1 C38.1 C39.1 C40.1 C41.1 C42.1 C47.1 C49.1 C52.1 C54.1 C56.1 P4.17 P8.1(6) P10.1 R17.2 R18.2 R27.1 R30.2 R31.2 R33.2 R39.1 R58.2 U5.7(VDD#7) U5.8(VDDA) U5.16(VDD#16) U5.26(VDD#26) U5.28(VDD#28) U5.39(VDD#39) U5.47(VDD#47) U5.51(VDD#51) U5.52(VDD#52) U5.69(VDD#69) U5.79(VDD#79) U5.90(VDD#90) U5.101(VDD#101) U5.113(VDD#113) U5.122(VDD#122) U7.3(OUT#3) U7.4(OUT#4) U8.3(VCCA) U8.4(1DIR) U9.3(VCCA) U9.4(1DIR) U10.3(VCCA) U10.4(1DIR)
N949215: R17.1 R20.1 R21.1 U5.70(NRST)
N949243: R30.1 U5.60(PK7)
N949263: C47.2 R33.1 R34.2 U7.5(FB)
N949375: R28.2 U5.59(RBIAS)
N949517: R22.1 R24.1 U5.1(PD0/AIN15)
N949687: C34.1 U5.89(OSC1) Y3.3
N949695: C33.1 U5.88(OSC0) Y3.1
N950083: C32.1 C50.1 R18.1 U5.9(VREFA+) U6.3(CATHODE)
N950235: R19.2 U5.95(PB0/USB0ID)
N951001: R39.2 U5.63(PK4)
N951013: R29.1 U5.61(PK6)
N951017: R27.2 U5.62(PK5)
N952443: C46.1 R31.1 U5.68(VBAT)
N1004371: R23.2 U5.3(PD2/AIN13)
N1004534: R25.2 U5.4(PD3/AIN12)
N1013277: U1.46(X24M_N) Y2.3
N1013855: C22.1 L22.2 L23.2 U1.2(RF_N)
N1013859: C11.2 L12.1 L22.1 U1.1(RF_P)
N1013899: C12.1 C22.2 L12.2 L13.1
N1013931: C13.1 L13.2 L14.1
N1013977: A1.1 C58.1 R12.2
N1014101: C17.1 U1.4(X32K_Q1) Y1.1
N1014113: C18.1 U1.5(X32K_Q2) Y1.2
N1018952: U1.47(X24M_P) Y2.1
N1031635: CR6.1 J6.M1(SHIELD1) J6.M2(SHIELD2) R32.2
N1105722: CR1.2(A) R15.1
N1105771: CR2.2(A) R14.1
N1105824: P6.1 R14.2
N1106228: P6.3 R15.2
N1176544: J2.13 R46.1
N1176548: J2.15 R47.1
N1176568: J2.17 R48.1
N1177007: J2.19 R49.1
N1288065: R55.1 SW2.3
N1288098: R56.1 SW1.4
N1384129: R57.1 SW3.3
N1393569: C19.1 U1.23(DCOUPL)
N1403554: C21.1 L23.1 U1.3(RX_TX)
N1414078: C14.1 C15.1 L14.2
N1442334: R59.1 U4.3(NWP/SIO2)
N1442341: R60.1 U4.7(NRST/SIO3)
N1450387: C15.2 C24.1 R12.1 R13.1
N1456638: P11.1 R13.2
N1467198: C59.1 R66.2 U5.96(PB1/USB0VBUS)
N10367920: CR5.2(A) R25.1
N10368080: CR4.2(A) R23.1

Pads without a net: CR7 1; CR8 1; FIDU1 1; FIDU2 1; FIDU3 1; FIDU4 1; FIDU5 1; FIDU6 1; J1 18; J2 8; P5 7; P7 7; P8 7; U5 2 5 6 11 12 13 14 15 18 19 20 21 22 23 27 29 30 31 32 41 42 43 44 45 46 49 50 53 54 56 57 65 67 71 72 73 74 75 76 77 78 81 82 83 84 85 86 91 92 102 103 104 105 106 107 108 109 110 111 112 116 117 118 119 120 121 123 124 125 126 127 128; U6 2 4 5; U7 7; U8 14; U9 8; U10 14

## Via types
v1: diameter 0.4, hole 0.2, TOP to BOTTOM, 494 vias
v2: diameter 0.5, hole 0.201, TOP to BOTTOM, 28 vias

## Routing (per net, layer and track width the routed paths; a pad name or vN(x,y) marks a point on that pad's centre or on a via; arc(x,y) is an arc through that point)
+5V: length 55.4
  L3 w0.5: P4.20 8.92,49.54 J1.2 7.58,45.8 4.7,45.8 0.75,41.85 0.75,17.07 P2.1
GND: length 134
  TOP w0.15: C14.2 25.6,28.99 ; C14.2 25.1,28.8 ; C14.2 25.6,27.96 ; C14.2 24.6,27.96 ; C14.2 v1(25.1,27.9) ; C14.2 24.6,28.99 ; C13.2 25.64,30.8 ; C13.2 25,31.3 ; C13.2 25.64,31.8 ; C13.2 v1(25.8,31.3) ; 37.1,28.2 P11.2 ; v1(20.4,60.07) U8.16 19.91,60.61 U8.1 ; C21.2 26.2,35.79 ; C21.2 25.7,35.4 ; C21.2 25.2,34.76 ; C21.2 25.7,34.6 v1(25.8,34.5) ; C21.2 26.2,34.76 ; C21.2 25.2,35.79 ; P11.M2 37.9,29 ; P11.M2 36.75,30.65 36.7,30.7 ; P11.M2 v1(35.3,29) ; 21.8,38.3 22.2,38.3 ; 10.39,57.16 P4.21 ; P4.21 12.54,57.16 ; P4.21 11.46,58.24 ; P4.21 11.46,56.08 ; 22.76,33.4 C12.2 ; C12.2 v1(22.6,33.9) ; C12.2 22.76,34.4 ; C12.2 23.4,33.9 ; 28.07,35.2 28.07,35.22 v1(27.6,35.7) ; 10.39,54.62 P4.22 ; P4.22 11.46,53.54 ; P4.22 11.46,55.7 ; P4.22 12.54,54.62 ; 8.06,41.06 J1.4 7.85,41.92 ; 29,26.9 29,26.3 ; 29,26.3 28.5,26.8 ; 29,26.3 C58.2 v1(28.3,26.3) ; 26.5,37.5 26.3,37.7 ; 3,56.5 MH5.1 ; MH5.1 4.1,57.6 ; MH5.1 1.9,57.6 ; MH5.1 3,58.7 ; 22.19,36.6 C11.1 ; C11.1 22.9,37.1 ; C11.1 22.19,37.6 ; C11.1 v1(22.1,37.1) ; C11.1 23.21,37.6 ; C11.1 23.21,36.6 ; 36.7,26.7 36.75,26.75 P11.M1 ; 52.12,43.38 J2.2 ; J2.2 52.12,45.54 ; J2.2 53.2,44.46 ; 30.34,29.03 30.35,29.75 ; 30.35,29.75 29.63,29.75 ; 30.35,29.75 31.07,29.76 ; P11.M1 35.6,27.4 ; P11.M1 37.9,27.4 ; U9.1 28,60.69 27.91,60.6 U9.16 v1(28.4,60.07) ; U10.16 v1(24.4,60.07) ; 22.9,38.1 v1(22.9,38.8)
  TOP w0.5: J6.5 12.7,88.6
  L2 w0.15: 11.46,53.54 P4.22 ; P4.22 10.39,54.62 ; P4.22 12.54,54.62 ; P4.22 11.46,55.7 ; J1.4 10,41.92 ; J1.4 7.85,41.92 ; J1.4 8.92,40.84 ; J1.4 8.92,43 ; 52.12,43.38 J2.2 ; J2.2 51.05,44.46 ; J2.2 52.12,45.54 ; J2.2 53.2,44.46 ; 1.9,57.6 MH5.1 ; MH5.1 4.1,57.6 ; MH5.1 3,58.7 ; MH5.1 3,56.5 ; 2.5,90.55 MH3.1 4.65,92.7 ; 10.39,57.16 P4.21 ; P4.21 11.46,58.24 ; P4.21 12.54,57.16 ; P4.21 11.46,56.08 ; 53.65,92.7 MH4.1 55.8,90.55
  L2 w0.8: 1.3,26.8 1.3,21.6 P2.3 P2.2 ; 56.8,26.5 56.8,21.2 P1.3 P1.2
  BOTTOM w0.15: 51.05,44.46 J2.2 ; J2.2 52.12,43.38 ; J2.2 52.12,45.54 ; J2.2 53.2,44.46 ; 11.46,56.08 P4.21 ; P4.21 12.54,57.16 ; P4.21 11.46,58.24 ; P4.21 10.39,57.16 ; MH5.1 3,58.7 ; MH5.1 1.9,57.6 ; MH5.1 3,56.5 ; MH5.1 4.1,57.6 ; 7.85,41.92 J1.4 ; J1.4 8.92,43 ; J1.4 8.92,40.84 ; J1.4 10,41.92 ; 11.46,53.54 P4.22 ; P4.22 12.54,54.62 ; P4.22 11.46,55.7 ; P4.22 10.39,54.62
  vias: v1(1.1,43.9) v1(1.4,71) v1(1.4,45.9) v1(1.6,72.5) v1(1.6,67.6) v1(1.7,41) v1(2.1,87.28) v1(2.1,84.74) v1(2.3,74.4) v1(2.6,53.2) v1(2.7,33.8) v1(3.1,78.6) v1(3.3,42.5) v1(3.37,83.47) v1(3.5,37.7) v1(3.6,61.7) v1(4,81.3) v1(4.4,35.3) v1(4.8,82.3) v1(4.8,47.3) v1(4.8,30.7) v1(4.8,27.6) v1(4.9,51.6) v1(5,26.3) v1(5.1,71.3) v1(5.2,77.7) v1(5.3,86.9) v1(6,87.9) v1(6.4,62) v1(7.5,82.6) v1(8.3,30.5) v1(8.5,88.3) v1(9,65.2) v1(10,84.3) v1(10.1,52.8) v1(10.3,29.6) v1(10.4,33.3) v1(10.7,85.3) v1(10.8,81.2) v1(11.2,17.4) v1(11.2,12.7) v1(11.2,2.7) v1(11.3,62.1) v1(11.3,7.4) v1(11.8,78) v1(11.8,65.2) v1(12,10.9) v1(12.3,81.6) v1(12.3,51.7) v1(12.5,14.3) v1(12.5,5.4) v1(12.5,1.1) v1(12.8,16) v1(13.2,82.8) v1(13.5,88.2) v1(13.6,81.9) v1(13.8,87.3) v1(14,17.4) v1(14.1,58.7) v1(14.3,82.6) v1(14.3,40.5) v1(14.3,26.4) v1(14.4,36.9) v1(14.4,33.8) v1(14.4,30.9) v1(14.5,88.3) v1(15,12.2) v1(15.5,31.8) v1(15.5,7.4) v1(15.7,85.6) v1(15.8,87.4) v1(15.8,39.9) v1(15.8,29.4) v1(15.8,2.4) v1(16,34.5) v1(16.1,37.3) v1(16.2,43) v1(16.3,61.8) v1(16.3,38.6) v1(16.6,47.6) v1(16.6,16) v1(17.1,5.9) v1(17.3,78) v1(17.4,27.4) v1(17.6,81.4) v1(17.7,59) v1(17.7,55.6) v1(17.7,49.8) v1(17.7,10.9) v1(17.8,61.7) v1(17.9,71.3) v1(17.9,17.4) v1(18,75.4) v1(18,74.2) v1(18.12,39.5) v1(18.2,41.2) v1(18.3,42.7) v1(18.4,82.6) v1(18.4,47.6) v1(18.6,42) v1(18.6,37.5) v1(18.8,86.1) v1(19,26.3) v1(19.3,61.5) v1(19.3,61) v1(20,27.4) v1(20,1) v1(20.3,47.5) v1(20.3,43.1) v1(20.4,40.9) v1(20.5,39.4) v1(20.5,16) v1(20.6,38.7) v1(20.6,7.4) v1(20.7,63.9) v1(20.8,84.8) v1(20.8,29.1) v1(20.9,48.31) v1(20.9,43.2) v1(21.2,40.82) v1(21.2,12.3) v1(21.3,71.1) v1(21.4,38.7) v1(21.7,59.5) v1(21.8,87.8) v1(21.8,31.1) v1(21.8,29.5) v1(21.9,35.3) v1(21.9,27.5) v1(22.1,62.5) v1(22.1,60) v1(22.3,69.2) v1(22.33,36.54) v1(22.4,37.7) v1(22.4,26.5) v1(22.6,84.7) v1(22.6,76.7) v1(22.7,74.7) v1(22.7,34.5) v1(22.7,33.3) v1(22.8,48.82) v1(22.8,36.3) v1(22.8,32.7) v1(23,35.5) v1(23.1,61.8) v1(23.1,61.2) v1(23.1,29.9) v1(23.32,48.8) v1(23.3,17.3) v1(23.3,5.9) v1(23.4,32.1) v1(23.4,31.2) v1(23.5,29) v1(23.6,27.7) v1(23.7,52.3) v1(24,11) v1(24.1,2.5) v1(24.4,52.3) v1(24.5,49.2) v1(24.6,28.1) v1(24.9,63.5) v1(25,33.8) v1(25,30.5) v1(25.1,65.9) v1(25.2,32.9) v1(25.2,26.3) v1(25.3,87.8) v1(25.5,83.2) v1(25.6,93.4) v1(25.6,34) v1(25.6,31.8) v1(25.6,30.8) v1(25.7,78.9) v1(25.7,73.9) v1(25.66,28.1) v1(25.7,27.5) v1(26,52.3) v1(26,37.7) v1(26,16) v1(26.1,32.8) v1(26.2,30.5) v1(26.3,34.8) v1(26.37,36.11) v1(26.5,37) v1(26.5,35.6) v1(26.6,48.8) v1(26.6,26.3) v1(26.65,59.42) v1(26.7,34.1) v1(26.9,31.7) v1(26.9,7.5) v1(27.1,36.4) v1(27.2,30.5) v1(27.3,61.74) v1(27.3,61.2) v1(27.3,52.2) v1(27.4,68.2) v1(27.5,28.8) v1(27.7,27.5) v1(27.7,0.9) v1(27.9,34.1) v1(27.9,33) v1(28.4,26.9) v1(28.5,30.5) v1(28.5,17.4) v1(28.8,28.8) v1(28.8,27.9) v1(28.9,35.2) v1(28.9,31.3) v1(28.9,12.4) v1(29,27.1) v1(29.2,20.5) v1(29.3,30.2) v1(29.3,24.2) v1(29.7,60.1) v1(30.3,49.3) v1(30.5,64.1) v1(30.5,24.3) v1(30.5,6) v1(30.6,46.7) v1(30.6,35.1) v1(30.6,22.4) v1(30.6,18.4) v1(30.6,16) v1(30.7,27.1) v1(30.9,59.5) v1(30.9,31.8) v1(31,29.8) v1(31.1,47.57) v1(31.2,29) v1(31.2,26.2) v1(31.7,46.62) v1(31.7,30.5) v1(31.8,63.3) v1(31.8,35.2) v1(32,39.7) v1(32,27.2) v1(32.1,28.9) v1(32.1,26.2) v1(32.3,7.4) v1(32.3,2.5) v1(32.57,40) v1(32.8,34.2) v1(32.9,46.4) v1(33,54.6) v1(33,45.2) v1(33,32.6) v1(33,10.9) v1(33.1,48.4) v1(33.2,29) v1(33.3,58.8) v1(33.5,27.1) v1(33.5,26.5) v1(33.8,30.4) v1(34.1,46.5) v1(34.1,26.2) v1(34.2,94.2) v1(34.4,29) v1(34.4,27.4) v1(34.5,36.4) v1(34.8,5.9) v1(34.9,26.6) v1(35.2,27.5) v1(35.3,31.4) v1(35.6,63.6) v1(35.7,0.9) v1(35.8,51.9) v1(35.8,29.7) v1(35.8,26.6) v1(36,53.8) v1(36.4,7.5) v1(36.5,79.6) v1(37,26.3) v1(37.1,35.6) v1(37.3,29.8) v1(37.9,26.3) v1(38.3,34.6) v1(38.7,5.9) v1(38.8,35.68) v1(38.8,12.4) v1(38.9,27.8) v1(39.2,66.1) v1(39.6,62.3) v1(39.6,2.5) v1(40.04,51.34) v1(40.1,47.5) v1(40.3,43.9) v1(40.4,42.5) v1(40.5,39.8) v1(40.7,35.8) v1(40.7,34.9) v1(40.8,27.4) v1(40.8,26.3) v1(41.1,94) v1(41.6,7.5) v1(41.79,56.42) v1(42.3,47.6) v1(42.6,59.3) v1(42.9,11) v1(43.5,50.4) v1(43.5,37.1) v1(43.6,1) v1(44,39.9) v1(44.2,6) v1(44.3,26.2) v1(44.9,66.5) v1(45.2,31.2) v1(45.3,47.7) v1(45.5,12.5) v1(46,26.2) v1(46.2,61) v1(46.6,49.8) v1(46.6,2.4) v1(46.8,27.7) v1(47,7.5) v1(47.1,45.2) v1(47.1,10.3) v1(47.2,56.1) v1(47.5,33.7) v1(47.6,63.3) v1(47.6,36.2) v1(47.7,57.3) v1(47.9,5.9) v1(48,93.6) v1(48.1,1.1) v1(48.6,12.4) v1(48.6,7.6) v1(49,51.1) v1(50.8,64.7) v1(50.8,26.3) v1(51.5,49.3) v1(52.8,51.8) v1(53.3,50.6) v1(53.7,57) v1(53.8,61) v1(53.9,35) v1(53.9,26.2) v1(54,28.5) v1(54.3,43.1) v1(54.3,40.4) v1(54.9,26.2) v1(55.1,65.5) v1(56.1,55.4) v1(56.9,70.6) v1(56.9,61.3) v1(56.9,44.1) v1(56.9,35.2) v1(56.9,30) v1(56.9,28) v1(57.1,77.2) v1(57.1,39.2) v1(57.2,81.7) v1(57.3,88.2) v1(57.6,45.5) v2(13.2,86) v2(13.2,85.1) v2(13.2,84.2) v2(24.6,45.2) v2(24.6,44.2) v2(24.6,43.2) v2(24.6,42.2) v2(24.6,41.2) v2(25.6,45.2) v2(25.6,44.2) v2(25.6,43.2) v2(25.6,42.2) v2(25.6,41.2) v2(26.6,45.2) v2(26.6,44.2) v2(26.6,43.2) v2(26.6,42.2) v2(26.6,41.2) v2(27.6,45.2) v2(27.6,44.2) v2(27.6,43.2) v2(27.6,42.2) v2(27.6,41.2) v2(28.6,45.2) v2(28.6,44.2) v2(28.6,43.2) v2(28.6,42.2) v2(28.6,41.2)
VDDC: length 16.2
  TOP w0.2: U5.87 8.9,72.2 7.3,70.6 U5.115 2.5,70.6 C43.1 C44.1 C45.1
VDDR: length 25.8
  TOP w0.3: 22.14,39.4 22.65,39.4 23.2,39.95 U1.48 ; v1(19.76,42.47) 19.76,42.33 20.06,42.03 21.07,42.03 21.6,41.5 C16.1 22.1,41.9 U1.45
  TOP w0.4: 22.14,39.4 C9.1 v1(22.1,38.8)
  TOP w0.5: C8.1 L1.2 25.3,50 24.3,50 v1(24,49.7)
  L3 w0.4: v1(19.76,42.47) 19.76,40.64 20.45,39.95 21.48,39.95 22.1,39.33 v1(22.1,38.8)
  L3 w0.5: v1(24,49.7) 20.9,49.7 19.69,48.49 19.69,42.47 v1(19.76,42.47)
VDDS: length 37.4
  TOP w0.3: U1.22 31.12,44.9 31.42,45.2 v1(31.9,45.2) C4.1 ; U1.13 C3.1 ; C5.1 22.15,42.6 22.35,42.4 U1.44 ; R1.2 22.18,48 C6.1 C7.1 24.3,48 24.9,47.4 U1.34
  TOP w0.5: 21.9,48.4 21.9,50.09 22.61,50.8 FL1.1 ; 21.9,48.4 v1(21.6,48.4) ; 21.9,48.4 21.9,48.4 R1.2 21.9,47.6 ; v1(21.6,43.2) C5.1 ; C3.1 v1(31.2,39.8)
  L3 w0.5: v1(21.6,48.4) v1(21.6,43.2) 21.6,42 23.8,39.8 v1(31.2,39.8) 31.2,43.42 31.9,44.12 v1(31.9,45.2)
BP_RESET: length 17.7
  TOP w0.15: v1(47.8,40.9) 43.7,45 R52.2
  L3 w0.15: v1(47.8,40.9) 47.8,39.4 49.1,38.1 49.9,38.1 50.63,37.37 50.63,32.81 J2.11
CC1310_RESET: length 73.5
  TOP w0.15: P4.12 22.51,52.97 15.92,52.97 15.1,52.15 15.1,47.3 15.6,46.8 C20.1 R1.1 23.1,46.8 23.57,47.28 24.14,47.28 24.4,47.02 U1.35 ; CR8.2 38.6,49.8 v1(38.7,49.7) ; P5.10 46.9,53.7 48.59,55.39 48.87,55.67 50.34,55.67 51.3,54.71 51.3,52.8 45.1,46.6 R52.1 R51.2 v1(40.8,47.5)
  L3 w0.15: v1(40.8,47.5) 40.51,47.78 40.51,47.88 v1(38.7,49.7)
  BOTTOM w0.15: P4.12 25.81,52.97 39.22,52.97 40.8,51.4 v1(40.8,47.5)
CC1310_RXD: length 78.6
  TOP w0.15: U1.7 26.9,38.93 28.15,37.68 35.13,37.68 38.12,40.67 38.12,47.05 34.5,50.67 v1(34.5,51.8) ; 14.2,47.77 14.5,48.07 14.5,52.4 15.67,53.57 15.92,53.57 15.92,53.57 18.03,53.57 P4.16 ; 14.2,47.77 7.37,47.77 5,45.4 5,38.22 J1.7 ; 14.2,47.77 14.27,47.69 v1(14.27,47.4)
  L3 w0.15: v1(14.27,47.4) 14.56,47.69 14.56,47.93 17.5,50.88 33.57,50.88 v1(34.5,51.8)
CC1310_SWO: length 71
  TOP w0.15: J2.9 50.8,35.52 50.8,47.13 50.63,47.3 v1(50.63,47.7) 50.63,51.71 51.6,52.67 51.6,54.83 50.46,55.97 49.03,55.97 48.36,56.64 45.64,56.64 45,56 v1(44.6,56) ; v1(27.89,55.69) 27.89,53.18 27.9,53.17 v1(27.9,48.4) U1.28
  L3 w0.15: v1(50.63,47.7) 47.2,47.7 46.5,47 33.47,47 32.8,47.68 32.8,47.68 32.37,48.1 30.9,48.1 30.3,47.5 28.8,47.5 v1(27.9,48.4) ; P4.2 38.72,54.62 40.1,56 41.6,56 41.62,55.97 41.98,55.97 42,56 v1(44.6,56)
CC1310_TCK: length 60.3
  TOP w0.15: CR8.6 38.6,52.5 38.9,52.8 39.4,52.8 39.8,52.4 41.42,52.4 41.97,52.95 P5.4 41.97,54.45 41.42,55 39.8,55 v1(36.7,51.9) 36.7,49.87 38.14,48.43 38.8,48.43 39.33,47.9 39.33,47.48 39.32,47.47 39.32,40.17 36.1,36.95 36.1,33.27 37.5,31.88 38.4,31.88 40.9,29.38 40.9,28.71 41.7,27.91 R47.2 ; P4.8 29.24,53.59 29.4,53.44 U1.25
  L3 w0.15: P4.8 30.27,54.62 31.69,53.2 35.4,53.2 v1(36.7,51.9)
CC1310_TMS: length 54.8
  TOP w0.15: P4.10 26.7,53.59 26.7,53.59 v1(26.7,49.5) ; U1.24 v1(30.1,48) ; R46.2 41.7,29.22 41.08,29.84 40.86,29.84 38.53,32.18 37.62,32.18 36.4,33.4 36.4,36.82 39.62,40.05 39.62,47.35 39.63,47.35 39.63,47.78 39.63,47.78 39.63,48.03 38.93,48.72 38.27,48.72 37,49.99 37,51.3 v1(37.6,51.9) CR8.7 38.1,52.5 39.3,53.7 P5.2
  L3 w0.15: v1(26.7,49.5) 27.8,49.5 28.8,48.5 30.6,48.5 ; 30.6,48.5 32.4,48.5 32.68,48.22 33.4,47.5 34.1,47.5 34.38,47.77 34.38,48.18 37.6,51.4 v1(37.6,51.9) ; 30.6,48.5 v1(30.1,48)
CC1310_TXD: length 68.7
  TOP w0.15: J1.5 5.33,40.43 5.33,45.23 7,46.9 14.5,46.9 14.8,47.2 14.8,52.28 15.79,53.27 20.27,53.27 P4.14 ; U1.8 27.4,38.85 28.28,37.97 35,37.97 37.82,40.8 37.82,46.92 34.2,50.55 34.2,51.3 32,53.5 v1(30.1,53.5)
  L3 w0.15: P4.14 22.84,53.4 28.12,53.4 28.28,53.25 28.28,53.22 28.52,52.97 28.88,52.97 29.12,53.22 29.12,53.25 29.28,53.4 29.6,53.4 29.7,53.5 v1(30.1,53.5)
CC1310_VDD: length 169.1
  TOP w0.3: v1(38.3,32.6) 38.28,32.6 R11.2 ; 13.6,28.1 R3.2 ; R3.2 13.58,28.2 12.52,28.2 R2.2 ; R3.2 13.6,29 12.88,29.72 12.88,41.18 v1(14.7,43) ; R60.2 37.8,37.12 C30.1 ; C30.1 v1(37.2,36.4) ; C30.1 U4.8 ; v1(37.6,50.6) 37.6,49.93 38.43,49.1 P5.1 ; R59.2 40.62,32.98 v1(41,32.6) ; v1(15.6,51.8) v1(15.6,48.1)
  TOP w0.4: P10.3 46.28,51 41.85,51 40.7,49.85 P5.1 ; FL1.2 v1(21.8,52.2) 21.27,52.2 20.97,52.5 16.3,52.5 v1(15.6,51.8) ; v1(37.6,50.6) 37.6,50.94 37.81,51.15 CR8.8
  L3 w0.3: v1(38.3,32.6) v1(41,32.6) 41.01,32.6 ; v1(37.2,36.4) 37.54,36.06 37.55,36.06 41.01,32.6 ; 41.01,32.6 48.31,25.3 57.75,25.3 ; v1(15.6,48.1) 15.6,43.9 v1(14.7,43)
  L3 w0.4: P4.18 16.54,53.37 15.6,52.43 v1(15.6,51.8)
  L3 w0.5: J1.1 7.64,43.2 10.3,43.2 11.3,44.2 11.3,49.38 P4.18 ; P10.3 49.9,50 57.75,42.15 57.75,17.07 P1.1
  BOTTOM w0.4: v1(21.8,52.2) 23.03,50.97 37.23,50.97 v1(37.6,50.6)
DCDC_SW: length 1.9
  TOP w0.3: U1.33 25.4,47.61 L1.1
DIO1: length 79.5
  TOP w0.15: v1(13,28.7) 12.5,29.2 12.5,41.7 v1(13.6,42.8) ; U1.6 26.4,39 28.03,37.38 35.25,37.38 38.43,40.55 38.43,47.17 34.93,50.67 34.93,52.28 34.8,52.4 v1(34.4,52.4)
  L3 w0.15: v1(13,28.7) 13,25.68 J1.20 ; v1(34.4,52.4) 33.18,51.18 17.38,51.18 13.6,47.4 v1(13.6,42.8)
DIO4_SCL: length 74.5
  TOP w0.15: 11.9,27.3 R2.1 ; 11.9,27.3 11.9,28.4 12.2,28.7 12.2,42 v1(12.95,42.75) ; 11.9,27.3 11.6,27.3 9.8,25.5 7.74,25.5 J1.17 ; U1.9 27.9,38.78 28.4,38.28 34.88,38.28 37.53,40.92 37.53,46.8 32.38,51.94 32.38,52.01 v1(32.1,52.3)
  L3 w0.15: v1(32.1,52.3) 31.28,51.47 17.25,51.47 13.3,47.52 13.3,47.28 13.3,43.1 v1(12.95,42.75)
DIO5_SDA: length 81.3
  TOP w0.15: v1(12.4,26.3) 13.2,26.3 13.6,26.7 R3.1 ; v1(31.2,52.3) 32.68,50.82 33.07,50.82 37.22,46.67 37.22,41.05 34.75,38.57 28.72,38.57 28.4,38.9 U1.10
  L3 w0.15: 7.8,25.5 12,25.5 12.4,25.9 v1(12.4,26.3) ; 7.8,25.5 7.8,39.8 8.5,40.5 9.41,40.5 13,44.09 13,47.65 17.13,51.78 30.68,51.78 v1(31.2,52.3) ; 7.8,25.5 7.8,23.02 J1.19
DIO6_RLED: length 62.3
  TOP w0.15: v1(32.9,50.1) 33.3,50.1 36.8,46.6 v1(36.8,41.4) 36.8,41.05 34.63,38.88 29.07,38.88 28.9,39.05 U1.11
  L3 w0.15: v1(36.8,41.4) 37.32,41.92 J2.3 ; P6.2 17.4,48 19.97,50.57 32.43,50.57 v1(32.9,50.1)
DIO7_GLED: length 59.9
  TOP w0.15: U1.12 29.75,39.7 30.28,39.18 34.5,39.18 36.3,40.97 v1(36.3,43.2) 36.3,46.68 33.48,49.5 32.5,49.5 v1(32.1,49.9)
  L3 w0.15: J2.1 37.56,44.46 v1(36.3,43.2) ; v1(32.1,49.9) 31.72,50.28 20.5,50.28 19.2,48.97 19.2,37.61 19.94,36.87 P6.4
DIO8_MISO: length 30.6
  TOP w0.15: J2.14 50.94,30.4 40.8,30.4 38.97,32.23 v1(38.97,33.2) 38.97,33.37 39.1,33.5 U4.2 ; v1(33,39.6) 33,40.3 32.4,40.9 U1.14
  L3 w0.15: v1(33,39.6) 33,36.4 36.2,33.2 v1(38.97,33.2)
DIO9_MOSI: length 28.2
  TOP w0.15: v1(33.8,40.2) 32.6,41.4 U1.15 ; J2.12 51.07,32.81 47.59,32.81 v1(46,34.4) ; v1(40.8,38.3) 40.8,37.6 40.1,36.9 U4.5
  L3 w0.15: v1(33.8,40.2) 38.9,40.2 v1(40.8,38.3) 44.7,34.4 v1(46,34.4)
DIO10_SCLK: length 72
  TOP w0.15: 34.6,40.3 34.9,40.3 35.8,41.2 35.8,46.75 33.35,49.2 31.9,49.2 30.49,50.62 30.49,52.14 v1(30.2,52.43) ; 34.6,40.3 34.4,40.3 32.8,41.9 U1.16 ; 34.6,40.3 34.4,40.1 v1(34.4,39.7) ; v1(40.3,37.8) 39.6,37.1 U4.6
  L3 w0.15: J1.13 7.5,30.34 7.5,40 8.3,40.8 9.29,40.8 12.7,44.21 12.7,47.77 17.73,52.8 27.85,52.8 28.27,52.38 29.13,52.38 29.55,52.8 29.77,52.8 29.8,52.78 29.85,52.78 v1(30.2,52.43) ; v1(40.3,37.8) 38.4,39.7 v1(34.4,39.7)
DIO11_CS: length 24.9
  TOP w0.15: U1.17 v1(35,42.4)
  L3 w0.15: v1(35,42.4) 37,42.4 37.7,43.1 50.2,43.1 50.8,42.5 50.8,40.7 J2.6
DIO12: length 23
  TOP w0.15: U1.18 v1(34.1,42.9)
  L3 w0.15: J2.4 50.63,43.41 37.51,43.41 36.8,42.7 35.5,42.7 35.3,42.9 v1(34.1,42.9)
DIO13_BTN1: length 85.7
  TOP w0.15: v1(12.7,48.7) R56.2 5.9,48.7 ; U1.19 v1(34.6,43.4) 35.4,44.2 35.4,46.5 v1(33.95,47.95)
  L3 w0.15: v1(33.95,47.95) 33.95,49.85 35.4,51.3 35.4,51.7 35.38,51.72 35.38,52.08 35.4,52.1 35.4,52.38 34.88,52.9 31.57,52.9 31.37,53.1 30.3,53.1 30.28,53.07 29.92,53.07 29.9,53.1 29.43,53.1 29,52.68 28.4,52.68 27.97,53.1 17.6,53.1 13.2,48.7 v1(12.7,48.7) ; v1(34.6,43.4) 36.8,45.6 46.9,45.6 46.92,45.62 47.28,45.62 47.3,45.6 52.5,45.6 53.47,44.62 53.47,28.03 J2.16
DIO14_BTN2: length 52.3
  TOP w0.15: J2.18 54.74,24.14 55.5,24.9 55.5,45.9 ; v1(34.6,44.3) 34.2,43.9 U1.20 ; 55.5,45.9 54.1,45.9 53.3,46.7 v1(51.3,46.7) ; 55.5,45.9 55.62,46.02 R55.2
  L3 w0.15: v1(51.3,46.7) 47.9,46.7 47.2,46 36.3,46 v1(34.6,44.3)
DIO15: length 52.5
  TOP w0.15: v1(34.6,45.5) 33.5,44.4 U1.21 ; J2.20 53.6,21.6 56.1,24.1 v1(56.1,42.3)
  L3 w0.15: v1(56.1,42.3) 55.81,42.59 55.81,42.79 51.48,47.12 51.4,47.2 47.5,47.2 46.8,46.5 35.6,46.5 v1(34.6,45.5)
DIO16_TDO: length 67.6
  TOP w0.15: U1.26 28.9,53.2 v1(28.7,53.4) ; 36.24,52.7 P4.4 ; 36.24,52.7 36.9,52.7 39.5,55.3 42.39,55.3 43.24,54.45 P5.6 43.24,52.47 42.67,51.9 CR8.5 ; 36.24,52.7 36.24,49.9 38.02,48.12 38.68,48.12 39.03,47.78 39.03,40.3 35.8,37.07 35.8,33.15 37.37,31.57 38.28,31.57 40.3,29.55 40.3,25.53 41.7,24.12 R48.2
  L3 w0.15: P4.4 33.27,55.67 28.67,55.67 28.19,55.19 28.19,53.91 v1(28.7,53.4)
DIO17_TDI: length 71.6
  TOP w0.15: R49.2 41.7,22.3 40,24 40,29.43 38.15,31.28 37.12,31.28 35.5,32.9 35.5,37.2 38.72,40.42 38.72,47.47 v1(38.5,47.7) ; P4.6 30.7,55.7 28.7,55.7 28.19,55.19 28.19,53.31 28.4,53.1 U1.27 ; CR8.3 v1(39.7,50.4) 40.9,51.6 43.16,51.6 44.51,52.95 P5.8 44.51,55.19 44.1,55.6 39,55.6 v1(38.6,55.2)
  L3 w0.15: v1(38.5,47.7) 38.22,47.99 38.22,49.91 38.7,50.4 v1(39.7,50.4) ; v1(38.6,55.2) 38,55.8 35.97,55.8 35.37,55.2 35.37,54.19 34.76,53.57 32.83,53.57 P4.6
DIO19_CTS: length 31.7
  TOP w0.15: U1.29 v1(27.4,48.7)
  L3 w0.15: J2.7 45.62,40.8 35.6,40.8 33.6,42.8 33.6,46.4 32.88,47.12 28.38,47.12 27.4,48.1 v1(27.4,48.7)
DIO20_FLASH_CS: length 37.2
  TOP w0.15: U1.30 v1(26.9,48.1) ; J2.5 48.56,39.38 43.62,34.45 38.86,34.45 38.6,34.19 U4.1 R11.1 37.4,34.4 v1(37.1,34.4)
  L3 w0.15: v1(37.1,34.4) 35.6,34.4 34,36 34,39.4 32.5,40.9 32.5,45.8 32.1,46.2 28.8,46.2 v1(26.9,48.1)
DIO21: length 38.2
  TOP w0.15: U1.31 v1(26.4,47.38)
  BOTTOM w0.15: J1.15 7.7,28 9.8,28 11,29.2 11,44.3 13.2,46.5 25.52,46.5 v1(26.4,47.38)
DIO22: length 30.8
  TOP w0.15: U1.32 25.9,47.4 25.91,47.41 v1(25.91,47.56)
  BOTTOM w0.15: v1(25.91,47.56) 25.14,46.8 13.07,46.8 10.7,44.43 10.7,36.2 10.2,35.7 7.78,35.7 J1.9
DIO23_ANALOG: length 19.5
  TOP w0.15: J1.3 7.76,43.3 9.77,43.3 12.77,46.3 23.2,46.3 23.5,46.6 U1.36
DIO24_ANALOG: length 27.7
  TOP w0.15: U1.37 12.85,45.9 10.35,43.4 10.3,43.4 10,43.1 10,41.2 9.34,40.54 8.44,40.54 7.8,39.9 7.8,33.18 J1.11
DIO25_ANALOG: length 18
  TOP w0.15: U1.38 12.78,45.4 10.4,43.02 10.4,42.78 10.4,40.86 J1.6
DIO26_ANALOG: length 20.7
  TOP w0.15: J1.8 9.95,36.84 10.7,37.59 10.7,42.9 12.7,44.9 U1.39
DIO27_ANALOG: length 23.2
  TOP w0.15: J1.10 10.3,34.3 11,35 11,42.78 12.82,44.6 22.27,44.6 22.47,44.4 U1.40
DIO28_ANALOG: length 25.2
  TOP w0.15: J1.12 9.95,31.76 11.3,33.11 11.3,42.65 12.95,44.3 22.15,44.3 22.55,43.9 U1.41
DIO29_ANALOG: length 26.9
  TOP w0.15: U1.42 22.55,43.4 21.95,44 13.07,44 11.6,42.53 11.6,31.9 J1.14
DIO30_ANALOG: length 29.2
  TOP w0.15: U1.43 22.55,42.9 22.4,43.05 22.4,43.12 21.82,43.7 13.2,43.7 11.9,42.4 11.9,29.66 J1.16
IRSTN: length 16.5
  TOP w0.15: v1(3.5,82.1) 5.3,83.9 v1(5.3,85.5) ; v1(6.82,85.5) 9.5,85.5 11.2,83.8 11.2,81.5 11.8,80.9 R20.2 14.4,80.9
  L3 w0.15: v1(5.3,85.5) v1(6.82,85.5)
ITCK: length 12.2
  TOP w0.15: v1(2.1,86) 0.8,84.7 0.8,77.8 2,76.6 U5.100
ITDI: length 10.1
  TOP w0.15: U5.98 2.05,77.4 1.44,78.01 1.44,81.14 2.8,82.5 2.8,84.12 v1(3.38,84.7)
ITDO: length 13.2
  TOP w0.15: v1(3.4,87.3) 4.8,85.9 4.8,84.08 1.74,81.01 1.74,78.14 2.08,77.8 U5.97
ITMS: length 9
  TOP w0.15: 3.8,77 2.03,77 1.14,77.89 1.14,82.54 v1(2.1,83.5)
LP_RESET: length 24.8
  TOP w0.15: R51.1 41.71,45 46.6,40.1 v1(46.6,38.1)
  L3 w0.15: v1(46.6,38.1) 46.6,31.7 47.7,30.6 50.2,30.6 50.9,31.3 50.9,32.05 52.12,33.27 J2.10
USB_DM: length 14.1
  TOP w0.15: J6.2 v1(10.75,88.9) 10.8,88.85 CR6.5 ; v1(8.7,86.9) 7.3,86.9 6.4,86 6.4,80.1 6.5,80 U5.93
  L3 w0.15: v1(10.75,88.9) 10.75,88.88 9.06,87.19 8.99,87.19 v1(8.7,86.9)
USB_DP: length 15.5
  TOP w0.15: J6.3 v1(11.4,88.9) 11.3,88.8 11.3,88.19 ; v1(9.4,86.9) 8.91,87.38 7.36,87.38 6.1,86.12 U5.94
  L3 w0.15: v1(9.4,86.9) v1(11.4,88.9)
USB_ID: length 14.1
  TOP w0.15: CR6.2 v1(10.8,87) 10.1,87 9.4,87.7 7.25,87.7 5.8,86.25 5.8,82.88 5.6,82.68 R19.1 ; J6.4 v1(12.05,88.9)
  L3 w0.15: v1(10.8,87) 10.8,87.65 v1(12.05,88.9)
USB_VBUS: length 56
  TOP w0.15: U7.8 v1(14.7,86.58) ; v1(4.6,63.1) 4.38,62.87 R22.2 ; R66.1 3.69,80.3 3.29,79.91 3.21,79.91 v1(2.6,79.3)
  TOP w0.3: U7.2 U7.1 11.7,86.58 12.2,87.08 C48.1 ; CR6.6 10.3,88.67 10.1,88.87 v1(10.1,88.9) J6.1
  TOP w0.5: v1(12.2,87.9) C48.1
  L3 w0.5: 0.75,79.4 0.85,79.3 v1(2.6,79.3) ; 0.75,79.4 0.75,84.24 1.85,85.34 3.94,85.34 4.7,86.1 11.22,86.1 ; 0.75,79.4 0.75,65.95 3.6,63.1 v1(4.6,63.1) 4.6,62.3 7.6,59.3 11.86,59.3 P4.19
V-SENSE: length 40.7
  TOP w0.15: U9.2 C57.1 v1(29.9,61.1) ; v1(21.7,61.1) C53.1 U8.2 ; v1(25.7,61.1) C55.1 U10.2
  TOP w0.3: v1(29.9,61.1) 36.7,61.1 37.6,62 38.45,62 38.55,61.9 ; 38.55,61.9 CR7.8 ; 38.55,61.9 38.55,62.85 39.8,64.1 44.94,64.1 45.76,63.28 P7.1 46.47,62.53 48.3,60.7 48.3,58.76 P10.2
  L3 w0.3: v1(21.7,61.1) 22.1,60.7 25.3,60.7 v1(25.7,61.1) 26.1,60.7 28.8,60.7 29.2,61.1 v1(29.9,61.1)
XDS_RESET: length 11.5
  TOP w0.15: v1(23.51,63.7) U10.6 23.51,61.99 23.53,61.98 23.53,60.96 23.78,60.7 U10.1 ; U5.40 R58.1 21.3,68.19 21.8,67.69 21.8,66.7 v1(22.8,65.7)
  L3 w0.15: v1(23.51,63.7) 23.79,63.99 23.79,65.4 23.5,65.7 v1(22.8,65.7)
XDS_RESET_LS: length 62.5
  TOP w0.15: v1(17,90.3) R57.2 17.6,90.3 ; 40.68,57.93 38.87,57.93 37.1,59.7 37.1,60.38 37.32,60.6 ; P4.11 24.16,58.44 24,58.6 v1(24,59) 23.51,59.49 U10.15 ; 37.32,60.6 v1(34.6,60.6) ; 37.32,60.6 CR7.2
  L3 w0.15: v1(24,59) 26.47,59 26.47,59 26.83,59 27.03,59.2 29.7,59.2 31.1,60.6 ; 31.1,60.6 31.1,61.7 23.74,69.06 23.74,89.34 22.78,90.3 v1(17,90.3) ; 31.1,60.6 v1(34.6,60.6)
XDS_RX: length 3.1
  TOP w0.15: U8.8 18.71,62.84 19.2,63.33 U5.33
XDS_RX_LS: length 10.6
  TOP w0.15: R61.2 21.72,58.29 21.62,58.19 P4.13 21.6,57.16 21.6,56.3 21.2,55.9 18.5,55.9 17.9,56.5 17.9,57.9 18.71,58.71 U8.13
XDS_SWO: length 7.2
  TOP w0.15: U5.25 14.9,64.75 15.05,64.9 17.95,64.9 18.1,64.75 18.1,62.3 18.5,61.9 U8.9
XDS_SWO_LS: length 24.7
  TOP w0.15: P4.1 35.5,58.52 35.5,59.2 ; v1(32.5,60.1) 35.35,60.1 35.5,59.95 35.5,59.2 ; U8.12 v1(17.8,60.7) ; 34.8,59.2 R62.2 35.5,59.2
  L3 w0.15: v1(17.8,60.7) 17.8,59.7 19,58.5 26.8,58.5 27.11,58.81 31.21,58.81 v1(32.5,60.1)
XDS_TCK: length 10.4
  TOP w0.15: U5.35 20.15,66.2 20.7,65.65 v1(20.7,65.2) ; v1(23.3,65.2) 23.69,64.81 25.78,64.81 27.51,63.09 U9.6
  L3 w0.15: v1(23.3,65.2) v1(20.7,65.2)
XDS_TCK_LS: length 28.7
  TOP w0.15: U9.15 27.51,59.55 28.52,58.54 28.52,57.89 P4.7 ; CR7.6 43.9,60.6 44.49,60.01 P7.4 44.49,56.69 43.8,56 41.97,56 41.97,56 41.61,56 41.61,56 38.8,56 v1(38.4,56.4)
  L3 w0.15: P4.7 30.3,56.1 38.1,56.1 v1(38.4,56.4)
XDS_TDI: length 10.2
  TOP w0.15: U9.7 27.11,63.05 25.66,64.5 23.3,64.5 20.4,67.4 U5.38
XDS_TDI_LS: length 26.3
  TOP w0.15: U9.14 27.11,59.39 28.19,58.31 28.19,56.73 28.81,56.11 31.76,56.11 31.78,56.13 ; 31.78,56.13 P4.5 ; 31.78,56.13 31.81,56.11 37.3,56.11 37.32,56.13 37.33,56.13 38.03,56.82 38.68,56.82 38.9,56.6 41.37,56.6 41.95,57.18 P7.8 41.95,58.68 41.37,59.26 40.44,59.26 40.08,58.9 38.53,58.9 37.8,59.62 CR7.3
XDS_TDO: length 10.1
  TOP w0.15: U9.9 26.3,62.1 26.3,63.3 25.4,64.2 23.1,64.2 20.3,67 19.2,67
XDS_TDO_LS: length 25.4
  TOP w0.15: v1(27.77,58.08) 26.85,59 26.4,59 26.03,59.37 26.03,60.46 26.27,60.7 U9.12 ; R63.2 43.22,57.93 P7.6 43.22,59.58 42.7,60.1 v1(40.1,60.1) CR7.5
  L3 w0.15: v1(27.77,58.08) 28.17,58.08 28.29,58.21 33.27,58.21 P4.3 35.56,58.4 38.8,58.4 40.1,59.7 v1(40.1,60.1)
XDS_TMS: length 6.1
  TOP w0.15: U10.8 22.71,64.09 20.2,66.6 U5.36
XDS_TMS_DIR: length 12.8
  TOP w0.15: U5.24 14.5,64.85 14.85,65.2 18.07,65.2 18.6,64.68 v1(18.6,63.5) ; U10.5 23.91,63.11 v1(24,63.2)
  L3 w0.15: v1(24,63.2) 18.9,63.2 v1(18.6,63.5)
XDS_TMS_LS: length 33.4
  TOP w0.15: R65.2 46.36,58.06 46.24,57.93 P7.2 45.76,60.14 44.8,61.1 v1(40.1,61.1) CR7.7 ; P4.9 25.65,56.11 23.73,56.11 22.71,57.13 U10.13
  L3 w0.15: v1(40.1,61.1) 36.1,61.1 35.18,60.18 33.28,60.18 31.61,58.51 27.41,58.51 26.7,57.8 P4.9
XDS_TX: length 4.5
  TOP w0.15: U5.34 20.05,65.8 20.2,65.65 20.2,65.2 19.51,64.51 U8.6
XDS_TX_LS: length 3.1
  TOP w0.15: U8.15 19.51,58.62 19.08,58.19 P4.15
XDS_VCC: length 87.6
  TOP w0.15: v1(20.7,67.7) 21.13,67.28 R58.2 ; v1(8.9,61.1) R18.2 8.9,61.7 8.8,61.6 C42.1 ; U8.3 U8.4 C52.1 v1(21.7,61.9) ; v1(16.6,85.5) C47.1 17.05,84.9 17.08,84.92 R33.2 ; 21.9,75.7 R30.2 v1(22.61,75.7) ; C37.1 2.4,76.2 ; U9.3 U9.4 C56.1 ; U10.3 U10.4 C54.1 v1(25.7,61.9) ; R17.2 17.12,82.62 v1(17.1,82.65)
  TOP w0.2: v1(22.3,72.6) C40.1 C39.1 U5.51 U5.52 ; U5.69 16.1,80.35 16.2,80.45 C38.1 16.21,80.9 16.7,81.39 16.7,81.49 17.11,81.9 R17.2 ; U5.39 20.6,67.8 v1(20.7,67.7) ; v1(1.65,71.5) C36.1 2.4,71.4 U5.113 ; 15.5,62.5 C35.1 v1(15.5,61.6) ; 15.5,62.5 15.3,62.7 U5.26 ; 15.5,62.5 15.68,62.5 16.1,62.92 U5.28 ; U5.7 U5.8 8.1,62.7 C41.1 C42.1 ; U5.16 11.3,63 v1(11.5,62.8) ; 19.2,71 v1(20.26,71) ; U5.79 v1(12.1,80.36) ; v1(7.6,80.4) 7.7,80.3 U5.90 ; U5.122 v1(2.74,67.8) ; v1(20.71,80.9) R31.2 20,80.9 ; v1(1.75,76) C37.1 ; v1(21.9,79) R39.1 R27.1 ; 2.4,76.2 U5.101
  TOP w0.3: P10.1 49.9,63.5 48.8,64.6 39.5,64.6 36.8,61.9 v1(29.9,61.9) C56.1 ; v1(11.7,82.3) C49.1 U7.4 U7.3 ; v1(15.5,61.6) 15.5,58.2 P4.17
  L3 w0.15: v1(16.6,85.5) 16.6,83.1
  L3 w0.3: v1(29.9,61.9) 29.56,62.24 26.04,62.24 v1(25.7,61.9) 25.2,62.4 22.71,62.4 22.31,62 22.28,62 22.18,61.9 v1(21.7,61.9) 21.22,61.9 21.12,62 19.09,62 17.69,63.4 17.6,63.4
  L3 w0.5: 15.2,61.2 15.23,61.2
  vias: v1(2,82.4)
N949215: length 3.8
  TOP w0.15: R17.1 R21.1 R20.1 15.7,80.4 U5.70
N949243: length 2.1
  TOP w0.15: U5.60 20.59,76.2 21.09,75.7 R30.1
N949263: length 3
  TOP w0.15: U7.5 15.53,84.15 R34.2 C47.2 17.05,83.98 17.08,84 R33.1
N949375: length 2.2
  TOP w0.15: U5.59 19.96,75.8 20.96,74.8 R28.2
N949517: length 2.3
  TOP w0.15: R24.1 R22.1 U5.1
N949687: length 6.3
  TOP w0.15: 7.9,84.9 7.9,84.5 7.3,83.9 Y3.3 7.3,83.6 8.18,82.72 8.18,80.33 8.1,80.25 U5.89
  TOP w0.2: C34.1 7.9,84.9
